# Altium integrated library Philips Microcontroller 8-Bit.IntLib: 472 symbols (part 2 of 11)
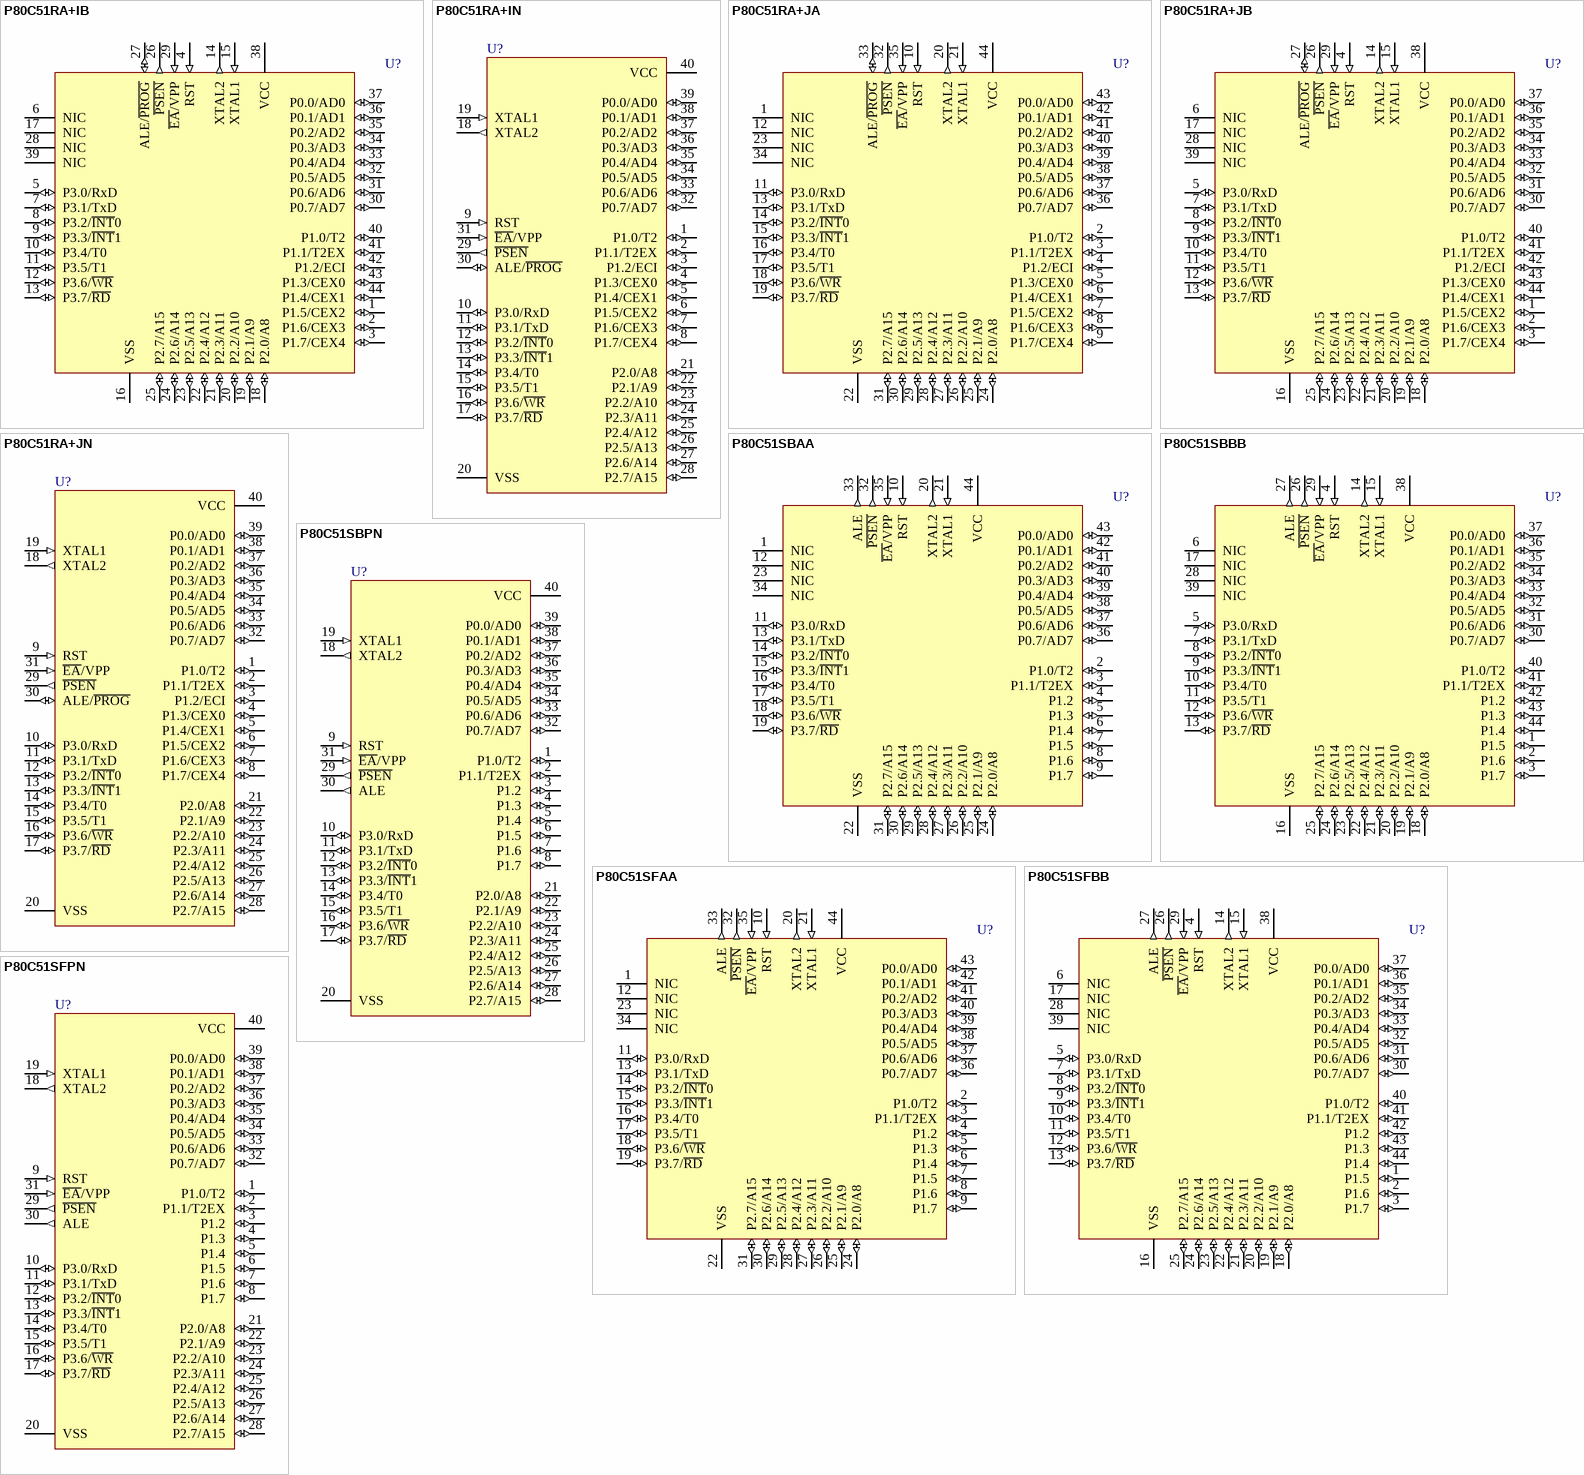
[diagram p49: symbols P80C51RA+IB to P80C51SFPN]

## P80C51RA+JB
designator U?
80C51 8-Bit Microcontroller Family: 512 B RAM, ROMless, 5V, Low Power, High Speed
footprint SOT307-2_N (QFP, 44-Leads, Body 10x10mm, Pitch 0.8mm, IPC Medium Density)
footprint SOT307-2_L (QFP, 44-Leads, Body 10x10mm, Pitch 0.8mm, IPC High Density)
footprint SOT307-2_M (QFP, 44-Leads, Body 10x10mm, Pitch 0.8mm, IPC Low Density)
pins: 1 P1.5/CEX2 (io), 2 P1.6/CEX3 (io), 3 P1.7/CEX4 (io), 4 RST (in), 5 P3.0/RxD (io), 6 NIC, 7 P3.1/TxD (io), 8 P3.2/~{INT}0 (io), 9 P3.3/~{INT}1 (io), 10 P3.4/T0 (io), 11 P3.5/T1 (io), 12 P3.6/~{WR} (io), 13 P3.7/~{RD} (io), 14 XTAL2 (out), 15 XTAL1 (in), 16 VSS (power), 17 NIC, 18 P2.0/A8 (io), 19 P2.1/A9 (io), 20 P2.2/A10 (io), 21 P2.3/A11 (io), 22 P2.4/A12 (io), 23 P2.5/A13 (io), 24 P2.6/A14 (io), 25 P2.7/A15 (io), 26 ~{PSEN} (out), 27 ALE/~{PROG} (io), 28 NIC, 29 ~{EA}/VPP (in), 30 P0.7/AD7 (io), 31 P0.6/AD6 (io), 32 P0.5/AD5 (io), 33 P0.4/AD4 (io), 34 P0.3/AD3 (io), 35 P0.2/AD2 (io), 36 P0.1/AD1 (io), 37 P0.0/AD0 (io), 38 VCC (power), 39 NIC, 40 P1.0/T2 (io), 41 P1.1/T2EX (io), 42 P1.2/ECI (io), 43 P1.3/CEX0 (io), 44 P1.4/CEX1 (io)

## P80C51RA+JN
designator U?
80C51 8-Bit Microcontroller Family: 512 B RAM, ROMless, 5V, Low Power, High Speed
footprint SOT129-1 (DIP, Plastic; 40 Leads; Row Spacing 15.24 mm; Pitch 2.54 mm)
pins: 1 P1.0/T2 (io), 2 P1.1/T2EX (io), 3 P1.2/ECI (io), 4 P1.3/CEX0 (io), 5 P1.4/CEX1 (io), 6 P1.5/CEX2 (io), 7 P1.6/CEX3 (io), 8 P1.7/CEX4 (io), 9 RST (in), 10 P3.0/RxD (io), 11 P3.1/TxD (io), 12 P3.2/~{INT}0 (io), 13 P3.3/~{INT}1 (io), 14 P3.4/T0 (io), 15 P3.5/T1 (io), 16 P3.6/~{WR} (io), 17 P3.7/~{RD} (io), 18 XTAL2 (out), 19 XTAL1 (in), 20 VSS (power), 21 P2.0/A8 (io), 22 P2.1/A9 (io), 23 P2.2/A10 (io), 24 P2.3/A11 (io), 25 P2.4/A12 (io), 26 P2.5/A13 (io), 27 P2.6/A14 (io), 28 P2.7/A15 (io), 29 ~{PSEN} (out), 30 ALE/~{PROG} (io), 31 ~{EA}/VPP (in), 32 P0.7/AD7 (io), 33 P0.6/AD6 (io), 34 P0.5/AD5 (io), 35 P0.4/AD4 (io), 36 P0.3/AD3 (io), 37 P0.2/AD2 (io), 38 P0.1/AD1 (io), 39 P0.0/AD0 (io), 40 VCC (power)

## P80C51SBAA
designator U?
80C51 8-Bit Microcontroller Family: 128 B RAM, 4 kB ROM, 2.7V-5.5V, Low Power, High Speed
footprint SOT187-2_N (Leaded Chip Carrier, 44-Leads, Body 16.6x16.6mm, Pitch 1.27mm, IPC Medium Density)
footprint SOT187-2_L (Leaded Chip Carrier, 44-Leads, Body 16.6x16.6mm, Pitch 1.27mm, IPC High Density)
footprint SOT187-2_M (Leaded Chip Carrier, 44-Leads, Body 16.6x16.6mm, Pitch 1.27mm, IPC Low Density)
pins: 1 NIC, 2 P1.0/T2 (io), 3 P1.1/T2EX (io), 4 P1.2 (io), 5 P1.3 (io), 6 P1.4 (io), 7 P1.5 (io), 8 P1.6 (io), 9 P1.7 (io), 10 RST (in), 11 P3.0/RxD (io), 12 NIC, 13 P3.1/TxD (io), 14 P3.2/~{INT}0 (io), 15 P3.3/~{INT}1 (io), 16 P3.4/T0 (io), 17 P3.5/T1 (io), 18 P3.6/~{WR} (io), 19 P3.7/~{RD} (io), 20 XTAL2 (out), 21 XTAL1 (in), 22 VSS (power), 23 NIC, 24 P2.0/A8 (io), 25 P2.1/A9 (io), 26 P2.2/A10 (io), 27 P2.3/A11 (io), 28 P2.4/A12 (io), 29 P2.5/A13 (io), 30 P2.6/A14 (io), 31 P2.7/A15 (io), 32 ~{PSEN} (out), 33 ALE (out), 34 NIC, 35 ~{EA}/VPP (in), 36 P0.7/AD7 (io), 37 P0.6/AD6 (io), 38 P0.5/AD5 (io), 39 P0.4/AD4 (io), 40 P0.3/AD3 (io), 41 P0.2/AD2 (io), 42 P0.1/AD1 (io), 43 P0.0/AD0 (io), 44 VCC (power)

## P80C51SBBB
designator U?
80C51 8-Bit Microcontroller Family: 128 B RAM, 4 kB ROM, 2.7V-5.5V, Low Power, High Speed
footprint SOT307-2_N (QFP, 44-Leads, Body 10x10mm, Pitch 0.8mm, IPC Medium Density)
footprint SOT307-2_L (QFP, 44-Leads, Body 10x10mm, Pitch 0.8mm, IPC High Density)
footprint SOT307-2_M (QFP, 44-Leads, Body 10x10mm, Pitch 0.8mm, IPC Low Density)
pins: 1 P1.5 (io), 2 P1.6 (io), 3 P1.7 (io), 4 RST (in), 5 P3.0/RxD (io), 6 NIC, 7 P3.1/TxD (io), 8 P3.2/~{INT}0 (io), 9 P3.3/~{INT}1 (io), 10 P3.4/T0 (io), 11 P3.5/T1 (io), 12 P3.6/~{WR} (io), 13 P3.7/~{RD} (io), 14 XTAL2 (out), 15 XTAL1 (in), 16 VSS (power), 17 NIC, 18 P2.0/A8 (io), 19 P2.1/A9 (io), 20 P2.2/A10 (io), 21 P2.3/A11 (io), 22 P2.4/A12 (io), 23 P2.5/A13 (io), 24 P2.6/A14 (io), 25 P2.7/A15 (io), 26 ~{PSEN} (out), 27 ALE (out), 28 NIC, 29 ~{EA}/VPP (in), 30 P0.7/AD7 (io), 31 P0.6/AD6 (io), 32 P0.5/AD5 (io), 33 P0.4/AD4 (io), 34 P0.3/AD3 (io), 35 P0.2/AD2 (io), 36 P0.1/AD1 (io), 37 P0.0/AD0 (io), 38 VCC (power), 39 NIC, 40 P1.0/T2 (io), 41 P1.1/T2EX (io), 42 P1.2 (io), 43 P1.3 (io), 44 P1.4 (io)

## P80C51SBPN
designator U?
80C51 8-Bit Microcontroller Family: 128 B RAM, 4 kB ROM, 2.7V-5.5V, Low Power, High Speed
footprint SOT129-1 (DIP, Plastic; 40 Leads; Row Spacing 15.24 mm; Pitch 2.54 mm)
pins: 1 P1.0/T2 (io), 2 P1.1/T2EX (io), 3 P1.2 (io), 4 P1.3 (io), 5 P1.4 (io), 6 P1.5 (io), 7 P1.6 (io), 8 P1.7 (io), 9 RST (in), 10 P3.0/RxD (io), 11 P3.1/TxD (io), 12 P3.2/~{INT}0 (io), 13 P3.3/~{INT}1 (io), 14 P3.4/T0 (io), 15 P3.5/T1 (io), 16 P3.6/~{WR} (io), 17 P3.7/~{RD} (io), 18 XTAL2 (out), 19 XTAL1 (in), 20 VSS (power), 21 P2.0/A8 (io), 22 P2.1/A9 (io), 23 P2.2/A10 (io), 24 P2.3/A11 (io), 25 P2.4/A12 (io), 26 P2.5/A13 (io), 27 P2.6/A14 (io), 28 P2.7/A15 (io), 29 ~{PSEN} (out), 30 ALE (out), 31 ~{EA}/VPP (in), 32 P0.7/AD7 (io), 33 P0.6/AD6 (io), 34 P0.5/AD5 (io), 35 P0.4/AD4 (io), 36 P0.3/AD3 (io), 37 P0.2/AD2 (io), 38 P0.1/AD1 (io), 39 P0.0/AD0 (io), 40 VCC (power)

## P80C51SFAA
designator U?
80C51 8-Bit Microcontroller Family: 128 B RAM, 4 kB ROM, 2.7V-5.5V, Low Power, High Speed
footprint SOT187-2_N (Leaded Chip Carrier, 44-Leads, Body 16.6x16.6mm, Pitch 1.27mm, IPC Medium Density)
footprint SOT187-2_L (Leaded Chip Carrier, 44-Leads, Body 16.6x16.6mm, Pitch 1.27mm, IPC High Density)
footprint SOT187-2_M (Leaded Chip Carrier, 44-Leads, Body 16.6x16.6mm, Pitch 1.27mm, IPC Low Density)
pins: 1 NIC, 2 P1.0/T2 (io), 3 P1.1/T2EX (io), 4 P1.2 (io), 5 P1.3 (io), 6 P1.4 (io), 7 P1.5 (io), 8 P1.6 (io), 9 P1.7 (io), 10 RST (in), 11 P3.0/RxD (io), 12 NIC, 13 P3.1/TxD (io), 14 P3.2/~{INT}0 (io), 15 P3.3/~{INT}1 (io), 16 P3.4/T0 (io), 17 P3.5/T1 (io), 18 P3.6/~{WR} (io), 19 P3.7/~{RD} (io), 20 XTAL2 (out), 21 XTAL1 (in), 22 VSS (power), 23 NIC, 24 P2.0/A8 (io), 25 P2.1/A9 (io), 26 P2.2/A10 (io), 27 P2.3/A11 (io), 28 P2.4/A12 (io), 29 P2.5/A13 (io), 30 P2.6/A14 (io), 31 P2.7/A15 (io), 32 ~{PSEN} (out), 33 ALE (out), 34 NIC, 35 ~{EA}/VPP (in), 36 P0.7/AD7 (io), 37 P0.6/AD6 (io), 38 P0.5/AD5 (io), 39 P0.4/AD4 (io), 40 P0.3/AD3 (io), 41 P0.2/AD2 (io), 42 P0.1/AD1 (io), 43 P0.0/AD0 (io), 44 VCC (power)

## P80C51SFBB
designator U?
80C51 8-Bit Microcontroller Family: 128 B RAM, 4 kB ROM, 2.7V-5.5V, Low Power, High Speed
footprint SOT307-2_N (QFP, 44-Leads, Body 10x10mm, Pitch 0.8mm, IPC Medium Density)
footprint SOT307-2_L (QFP, 44-Leads, Body 10x10mm, Pitch 0.8mm, IPC High Density)
footprint SOT307-2_M (QFP, 44-Leads, Body 10x10mm, Pitch 0.8mm, IPC Low Density)
pins: 1 P1.5 (io), 2 P1.6 (io), 3 P1.7 (io), 4 RST (in), 5 P3.0/RxD (io), 6 NIC, 7 P3.1/TxD (io), 8 P3.2/~{INT}0 (io), 9 P3.3/~{INT}1 (io), 10 P3.4/T0 (io), 11 P3.5/T1 (io), 12 P3.6/~{WR} (io), 13 P3.7/~{RD} (io), 14 XTAL2 (out), 15 XTAL1 (in), 16 VSS (power), 17 NIC, 18 P2.0/A8 (io), 19 P2.1/A9 (io), 20 P2.2/A10 (io), 21 P2.3/A11 (io), 22 P2.4/A12 (io), 23 P2.5/A13 (io), 24 P2.6/A14 (io), 25 P2.7/A15 (io), 26 ~{PSEN} (out), 27 ALE (out), 28 NIC, 29 ~{EA}/VPP (in), 30 P0.7/AD7 (io), 31 P0.6/AD6 (io), 32 P0.5/AD5 (io), 33 P0.4/AD4 (io), 34 P0.3/AD3 (io), 35 P0.2/AD2 (io), 36 P0.1/AD1 (io), 37 P0.0/AD0 (io), 38 VCC (power), 39 NIC, 40 P1.0/T2 (io), 41 P1.1/T2EX (io), 42 P1.2 (io), 43 P1.3 (io), 44 P1.4 (io)

## P80C51SFPN
designator U?
80C51 8-Bit Microcontroller Family: 128 B RAM, 4 kB ROM, 2.7V-5.5V, Low Power, High Speed
footprint SOT129-1 (DIP, Plastic; 40 Leads; Row Spacing 15.24 mm; Pitch 2.54 mm)
pins: 1 P1.0/T2 (io), 2 P1.1/T2EX (io), 3 P1.2 (io), 4 P1.3 (io), 5 P1.4 (io), 6 P1.5 (io), 7 P1.6 (io), 8 P1.7 (io), 9 RST (in), 10 P3.0/RxD (io), 11 P3.1/TxD (io), 12 P3.2/~{INT}0 (io), 13 P3.3/~{INT}1 (io), 14 P3.4/T0 (io), 15 P3.5/T1 (io), 16 P3.6/~{WR} (io), 17 P3.7/~{RD} (io), 18 XTAL2 (out), 19 XTAL1 (in), 20 VSS (power), 21 P2.0/A8 (io), 22 P2.1/A9 (io), 23 P2.2/A10 (io), 24 P2.3/A11 (io), 25 P2.4/A12 (io), 26 P2.5/A13 (io), 27 P2.6/A14 (io), 28 P2.7/A15 (io), 29 ~{PSEN} (out), 30 ALE (out), 31 ~{EA}/VPP (in), 32 P0.7/AD7 (io), 33 P0.6/AD6 (io), 34 P0.5/AD5 (io), 35 P0.4/AD4 (io), 36 P0.3/AD3 (io), 37 P0.2/AD2 (io), 38 P0.1/AD1 (io), 39 P0.0/AD0 (io), 40 VCC (power)

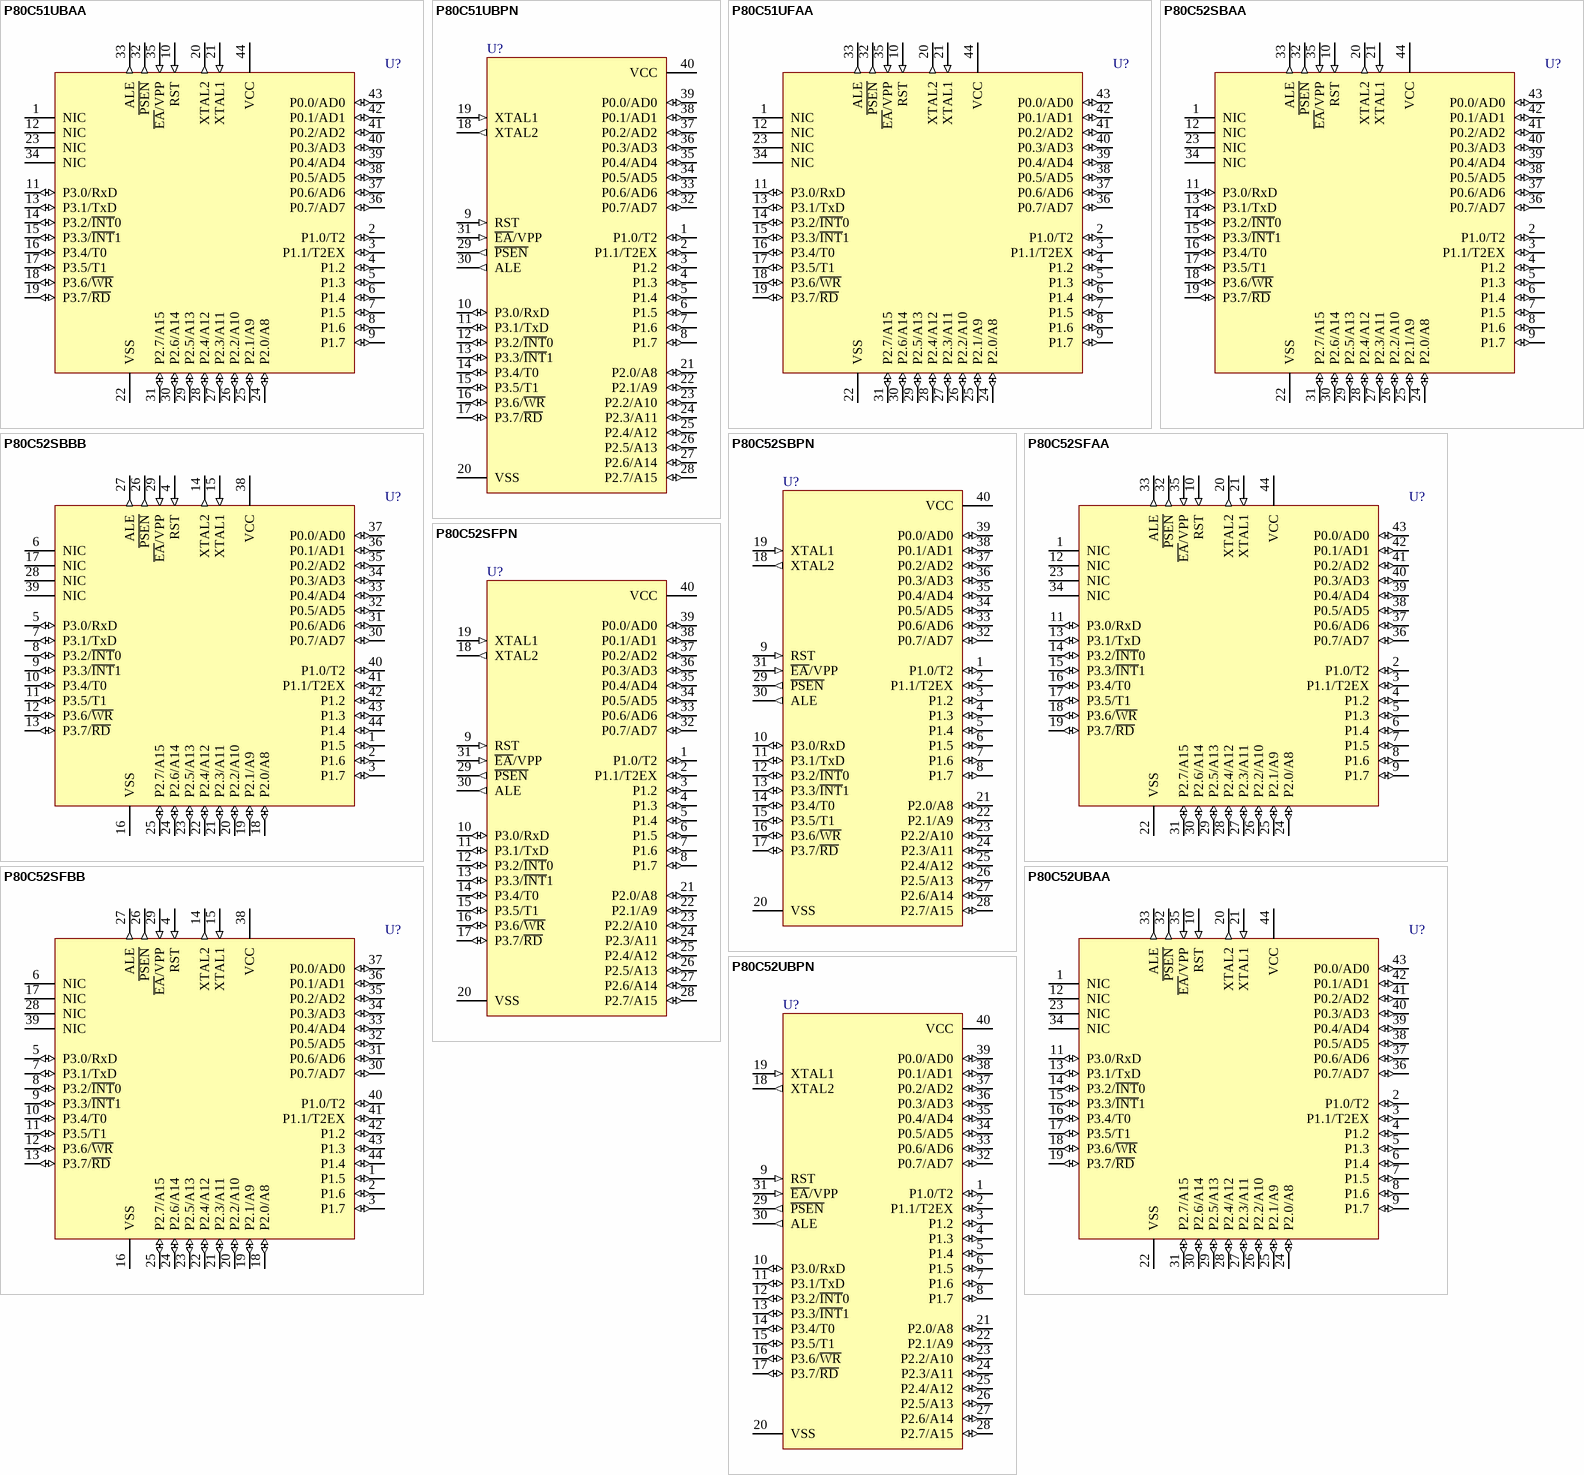
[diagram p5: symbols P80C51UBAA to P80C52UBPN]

## P80C51UBAA
designator U?
80C51 8-Bit Microcontroller Family: 128 B RAM, 4 kB ROM, 5V, Low Power, High Speed
footprint SOT187-2_N (Leaded Chip Carrier, 44-Leads, Body 16.6x16.6mm, Pitch 1.27mm, IPC Medium Density)
footprint SOT187-2_L (Leaded Chip Carrier, 44-Leads, Body 16.6x16.6mm, Pitch 1.27mm, IPC High Density)
footprint SOT187-2_M (Leaded Chip Carrier, 44-Leads, Body 16.6x16.6mm, Pitch 1.27mm, IPC Low Density)
pins: 1 NIC, 2 P1.0/T2 (io), 3 P1.1/T2EX (io), 4 P1.2 (io), 5 P1.3 (io), 6 P1.4 (io), 7 P1.5 (io), 8 P1.6 (io), 9 P1.7 (io), 10 RST (in), 11 P3.0/RxD (io), 12 NIC, 13 P3.1/TxD (io), 14 P3.2/~{INT}0 (io), 15 P3.3/~{INT}1 (io), 16 P3.4/T0 (io), 17 P3.5/T1 (io), 18 P3.6/~{WR} (io), 19 P3.7/~{RD} (io), 20 XTAL2 (out), 21 XTAL1 (in), 22 VSS (power), 23 NIC, 24 P2.0/A8 (io), 25 P2.1/A9 (io), 26 P2.2/A10 (io), 27 P2.3/A11 (io), 28 P2.4/A12 (io), 29 P2.5/A13 (io), 30 P2.6/A14 (io), 31 P2.7/A15 (io), 32 ~{PSEN} (out), 33 ALE (out), 34 NIC, 35 ~{EA}/VPP (in), 36 P0.7/AD7 (io), 37 P0.6/AD6 (io), 38 P0.5/AD5 (io), 39 P0.4/AD4 (io), 40 P0.3/AD3 (io), 41 P0.2/AD2 (io), 42 P0.1/AD1 (io), 43 P0.0/AD0 (io), 44 VCC (power)

## P80C51UBPN
designator U?
80C51 8-Bit Microcontroller Family: 128 B RAM, 4 kB ROM, 5V, Low Power, High Speed
footprint SOT129-1 (DIP, Plastic; 40 Leads; Row Spacing 15.24 mm; Pitch 2.54 mm)
pins: 1 P1.0/T2 (io), 2 P1.1/T2EX (io), 3 P1.2 (io), 4 P1.3 (io), 5 P1.4 (io), 6 P1.5 (io), 7 P1.6 (io), 8 P1.7 (io), 9 RST (in), 10 P3.0/RxD (io), 11 P3.1/TxD (io), 12 P3.2/~{INT}0 (io), 13 P3.3/~{INT}1 (io), 14 P3.4/T0 (io), 15 P3.5/T1 (io), 16 P3.6/~{WR} (io), 17 P3.7/~{RD} (io), 18 XTAL2 (out), 19 XTAL1 (in), 20 VSS (power), 21 P2.0/A8 (io), 22 P2.1/A9 (io), 23 P2.2/A10 (io), 24 P2.3/A11 (io), 25 P2.4/A12 (io), 26 P2.5/A13 (io), 27 P2.6/A14 (io), 28 P2.7/A15 (io), 29 ~{PSEN} (out), 30 ALE (out), 31 ~{EA}/VPP (in), 32 P0.7/AD7 (io), 33 P0.6/AD6 (io), 34 P0.5/AD5 (io), 35 P0.4/AD4 (io), 36 P0.3/AD3 (io), 37 P0.2/AD2 (io), 38 P0.1/AD1 (io), 39 P0.0/AD0 (io), 40 VCC (power)

## P80C51UFAA
designator U?
80C51 8-Bit Microcontroller Family: 128 B RAM, 4 kB ROM, 5V, Low Power, High Speed
footprint SOT187-2_N (Leaded Chip Carrier, 44-Leads, Body 16.6x16.6mm, Pitch 1.27mm, IPC Medium Density)
footprint SOT187-2_L (Leaded Chip Carrier, 44-Leads, Body 16.6x16.6mm, Pitch 1.27mm, IPC High Density)
footprint SOT187-2_M (Leaded Chip Carrier, 44-Leads, Body 16.6x16.6mm, Pitch 1.27mm, IPC Low Density)
pins: 1 NIC, 2 P1.0/T2 (io), 3 P1.1/T2EX (io), 4 P1.2 (io), 5 P1.3 (io), 6 P1.4 (io), 7 P1.5 (io), 8 P1.6 (io), 9 P1.7 (io), 10 RST (in), 11 P3.0/RxD (io), 12 NIC, 13 P3.1/TxD (io), 14 P3.2/~{INT}0 (io), 15 P3.3/~{INT}1 (io), 16 P3.4/T0 (io), 17 P3.5/T1 (io), 18 P3.6/~{WR} (io), 19 P3.7/~{RD} (io), 20 XTAL2 (out), 21 XTAL1 (in), 22 VSS (power), 23 NIC, 24 P2.0/A8 (io), 25 P2.1/A9 (io), 26 P2.2/A10 (io), 27 P2.3/A11 (io), 28 P2.4/A12 (io), 29 P2.5/A13 (io), 30 P2.6/A14 (io), 31 P2.7/A15 (io), 32 ~{PSEN} (out), 33 ALE (out), 34 NIC, 35 ~{EA}/VPP (in), 36 P0.7/AD7 (io), 37 P0.6/AD6 (io), 38 P0.5/AD5 (io), 39 P0.4/AD4 (io), 40 P0.3/AD3 (io), 41 P0.2/AD2 (io), 42 P0.1/AD1 (io), 43 P0.0/AD0 (io), 44 VCC (power)

## P80C52SBAA
designator U?
80C51 8-Bit Microcontroller Family: 256 B RAM, 8 kB ROM, 2.7V-5.5V, Low Power, High Speed
footprint SOT187-2_N (Leaded Chip Carrier, 44-Leads, Body 16.6x16.6mm, Pitch 1.27mm, IPC Medium Density)
footprint SOT187-2_L (Leaded Chip Carrier, 44-Leads, Body 16.6x16.6mm, Pitch 1.27mm, IPC High Density)
footprint SOT187-2_M (Leaded Chip Carrier, 44-Leads, Body 16.6x16.6mm, Pitch 1.27mm, IPC Low Density)
pins: 1 NIC, 2 P1.0/T2 (io), 3 P1.1/T2EX (io), 4 P1.2 (io), 5 P1.3 (io), 6 P1.4 (io), 7 P1.5 (io), 8 P1.6 (io), 9 P1.7 (io), 10 RST (in), 11 P3.0/RxD (io), 12 NIC, 13 P3.1/TxD (io), 14 P3.2/~{INT}0 (io), 15 P3.3/~{INT}1 (io), 16 P3.4/T0 (io), 17 P3.5/T1 (io), 18 P3.6/~{WR} (io), 19 P3.7/~{RD} (io), 20 XTAL2 (out), 21 XTAL1 (in), 22 VSS (power), 23 NIC, 24 P2.0/A8 (io), 25 P2.1/A9 (io), 26 P2.2/A10 (io), 27 P2.3/A11 (io), 28 P2.4/A12 (io), 29 P2.5/A13 (io), 30 P2.6/A14 (io), 31 P2.7/A15 (io), 32 ~{PSEN} (out), 33 ALE (out), 34 NIC, 35 ~{EA}/VPP (in), 36 P0.7/AD7 (io), 37 P0.6/AD6 (io), 38 P0.5/AD5 (io), 39 P0.4/AD4 (io), 40 P0.3/AD3 (io), 41 P0.2/AD2 (io), 42 P0.1/AD1 (io), 43 P0.0/AD0 (io), 44 VCC (power)

## P80C52SBBB
designator U?
80C51 8-Bit Microcontroller Family: 256 B RAM, 8 kB ROM, 2.7V-5.5V, Low Power, High Speed
footprint SOT307-2_N (QFP, 44-Leads, Body 10x10mm, Pitch 0.8mm, IPC Medium Density)
footprint SOT307-2_L (QFP, 44-Leads, Body 10x10mm, Pitch 0.8mm, IPC High Density)
footprint SOT307-2_M (QFP, 44-Leads, Body 10x10mm, Pitch 0.8mm, IPC Low Density)
pins: 1 P1.5 (io), 2 P1.6 (io), 3 P1.7 (io), 4 RST (in), 5 P3.0/RxD (io), 6 NIC, 7 P3.1/TxD (io), 8 P3.2/~{INT}0 (io), 9 P3.3/~{INT}1 (io), 10 P3.4/T0 (io), 11 P3.5/T1 (io), 12 P3.6/~{WR} (io), 13 P3.7/~{RD} (io), 14 XTAL2 (out), 15 XTAL1 (in), 16 VSS (power), 17 NIC, 18 P2.0/A8 (io), 19 P2.1/A9 (io), 20 P2.2/A10 (io), 21 P2.3/A11 (io), 22 P2.4/A12 (io), 23 P2.5/A13 (io), 24 P2.6/A14 (io), 25 P2.7/A15 (io), 26 ~{PSEN} (out), 27 ALE (out), 28 NIC, 29 ~{EA}/VPP (in), 30 P0.7/AD7 (io), 31 P0.6/AD6 (io), 32 P0.5/AD5 (io), 33 P0.4/AD4 (io), 34 P0.3/AD3 (io), 35 P0.2/AD2 (io), 36 P0.1/AD1 (io), 37 P0.0/AD0 (io), 38 VCC (power), 39 NIC, 40 P1.0/T2 (io), 41 P1.1/T2EX (io), 42 P1.2 (io), 43 P1.3 (io), 44 P1.4 (io)

## P80C52SBPN
designator U?
80C51 8-Bit Microcontroller Family: 256 B RAM, 8 kB ROM, 2.7V-5.5V, Low Power, High Speed
footprint SOT129-1 (DIP, Plastic; 40 Leads; Row Spacing 15.24 mm; Pitch 2.54 mm)
pins: 1 P1.0/T2 (io), 2 P1.1/T2EX (io), 3 P1.2 (io), 4 P1.3 (io), 5 P1.4 (io), 6 P1.5 (io), 7 P1.6 (io), 8 P1.7 (io), 9 RST (in), 10 P3.0/RxD (io), 11 P3.1/TxD (io), 12 P3.2/~{INT}0 (io), 13 P3.3/~{INT}1 (io), 14 P3.4/T0 (io), 15 P3.5/T1 (io), 16 P3.6/~{WR} (io), 17 P3.7/~{RD} (io), 18 XTAL2 (out), 19 XTAL1 (in), 20 VSS (power), 21 P2.0/A8 (io), 22 P2.1/A9 (io), 23 P2.2/A10 (io), 24 P2.3/A11 (io), 25 P2.4/A12 (io), 26 P2.5/A13 (io), 27 P2.6/A14 (io), 28 P2.7/A15 (io), 29 ~{PSEN} (out), 30 ALE (out), 31 ~{EA}/VPP (in), 32 P0.7/AD7 (io), 33 P0.6/AD6 (io), 34 P0.5/AD5 (io), 35 P0.4/AD4 (io), 36 P0.3/AD3 (io), 37 P0.2/AD2 (io), 38 P0.1/AD1 (io), 39 P0.0/AD0 (io), 40 VCC (power)

## P80C52SFAA
designator U?
80C51 8-Bit Microcontroller Family: 256 B RAM, 8 kB ROM, 2.7V-5.5V, Low Power, High Speed
footprint SOT187-2_N (Leaded Chip Carrier, 44-Leads, Body 16.6x16.6mm, Pitch 1.27mm, IPC Medium Density)
footprint SOT187-2_L (Leaded Chip Carrier, 44-Leads, Body 16.6x16.6mm, Pitch 1.27mm, IPC High Density)
footprint SOT187-2_M (Leaded Chip Carrier, 44-Leads, Body 16.6x16.6mm, Pitch 1.27mm, IPC Low Density)
pins: 1 NIC, 2 P1.0/T2 (io), 3 P1.1/T2EX (io), 4 P1.2 (io), 5 P1.3 (io), 6 P1.4 (io), 7 P1.5 (io), 8 P1.6 (io), 9 P1.7 (io), 10 RST (in), 11 P3.0/RxD (io), 12 NIC, 13 P3.1/TxD (io), 14 P3.2/~{INT}0 (io), 15 P3.3/~{INT}1 (io), 16 P3.4/T0 (io), 17 P3.5/T1 (io), 18 P3.6/~{WR} (io), 19 P3.7/~{RD} (io), 20 XTAL2 (out), 21 XTAL1 (in), 22 VSS (power), 23 NIC, 24 P2.0/A8 (io), 25 P2.1/A9 (io), 26 P2.2/A10 (io), 27 P2.3/A11 (io), 28 P2.4/A12 (io), 29 P2.5/A13 (io), 30 P2.6/A14 (io), 31 P2.7/A15 (io), 32 ~{PSEN} (out), 33 ALE (out), 34 NIC, 35 ~{EA}/VPP (in), 36 P0.7/AD7 (io), 37 P0.6/AD6 (io), 38 P0.5/AD5 (io), 39 P0.4/AD4 (io), 40 P0.3/AD3 (io), 41 P0.2/AD2 (io), 42 P0.1/AD1 (io), 43 P0.0/AD0 (io), 44 VCC (power)

## P80C52SFBB
designator U?
80C51 8-Bit Microcontroller Family: 256 B RAM, 8 kB ROM, 2.7V-5.5V, Low Power, High Speed
footprint SOT307-2_N (QFP, 44-Leads, Body 10x10mm, Pitch 0.8mm, IPC Medium Density)
footprint SOT307-2_L (QFP, 44-Leads, Body 10x10mm, Pitch 0.8mm, IPC High Density)
footprint SOT307-2_M (QFP, 44-Leads, Body 10x10mm, Pitch 0.8mm, IPC Low Density)
pins: 1 P1.5 (io), 2 P1.6 (io), 3 P1.7 (io), 4 RST (in), 5 P3.0/RxD (io), 6 NIC, 7 P3.1/TxD (io), 8 P3.2/~{INT}0 (io), 9 P3.3/~{INT}1 (io), 10 P3.4/T0 (io), 11 P3.5/T1 (io), 12 P3.6/~{WR} (io), 13 P3.7/~{RD} (io), 14 XTAL2 (out), 15 XTAL1 (in), 16 VSS (power), 17 NIC, 18 P2.0/A8 (io), 19 P2.1/A9 (io), 20 P2.2/A10 (io), 21 P2.3/A11 (io), 22 P2.4/A12 (io), 23 P2.5/A13 (io), 24 P2.6/A14 (io), 25 P2.7/A15 (io), 26 ~{PSEN} (out), 27 ALE (out), 28 NIC, 29 ~{EA}/VPP (in), 30 P0.7/AD7 (io), 31 P0.6/AD6 (io), 32 P0.5/AD5 (io), 33 P0.4/AD4 (io), 34 P0.3/AD3 (io), 35 P0.2/AD2 (io), 36 P0.1/AD1 (io), 37 P0.0/AD0 (io), 38 VCC (power), 39 NIC, 40 P1.0/T2 (io), 41 P1.1/T2EX (io), 42 P1.2 (io), 43 P1.3 (io), 44 P1.4 (io)

## P80C52SFPN
designator U?
80C51 8-Bit Microcontroller Family: 256 B RAM, 8 kB ROM, 2.7V-5.5V, Low Power, High Speed
footprint SOT129-1 (DIP, Plastic; 40 Leads; Row Spacing 15.24 mm; Pitch 2.54 mm)
pins: 1 P1.0/T2 (io), 2 P1.1/T2EX (io), 3 P1.2 (io), 4 P1.3 (io), 5 P1.4 (io), 6 P1.5 (io), 7 P1.6 (io), 8 P1.7 (io), 9 RST (in), 10 P3.0/RxD (io), 11 P3.1/TxD (io), 12 P3.2/~{INT}0 (io), 13 P3.3/~{INT}1 (io), 14 P3.4/T0 (io), 15 P3.5/T1 (io), 16 P3.6/~{WR} (io), 17 P3.7/~{RD} (io), 18 XTAL2 (out), 19 XTAL1 (in), 20 VSS (power), 21 P2.0/A8 (io), 22 P2.1/A9 (io), 23 P2.2/A10 (io), 24 P2.3/A11 (io), 25 P2.4/A12 (io), 26 P2.5/A13 (io), 27 P2.6/A14 (io), 28 P2.7/A15 (io), 29 ~{PSEN} (out), 30 ALE (out), 31 ~{EA}/VPP (in), 32 P0.7/AD7 (io), 33 P0.6/AD6 (io), 34 P0.5/AD5 (io), 35 P0.4/AD4 (io), 36 P0.3/AD3 (io), 37 P0.2/AD2 (io), 38 P0.1/AD1 (io), 39 P0.0/AD0 (io), 40 VCC (power)

## P80C52UBAA
designator U?
80C51 8-Bit Microcontroller Family: 256 B RAM, 8 kB ROM, 5V, Low Power, High Speed
footprint SOT187-2_N (Leaded Chip Carrier, 44-Leads, Body 16.6x16.6mm, Pitch 1.27mm, IPC Medium Density)
footprint SOT187-2_L (Leaded Chip Carrier, 44-Leads, Body 16.6x16.6mm, Pitch 1.27mm, IPC High Density)
footprint SOT187-2_M (Leaded Chip Carrier, 44-Leads, Body 16.6x16.6mm, Pitch 1.27mm, IPC Low Density)
pins: 1 NIC, 2 P1.0/T2 (io), 3 P1.1/T2EX (io), 4 P1.2 (io), 5 P1.3 (io), 6 P1.4 (io), 7 P1.5 (io), 8 P1.6 (io), 9 P1.7 (io), 10 RST (in), 11 P3.0/RxD (io), 12 NIC, 13 P3.1/TxD (io), 14 P3.2/~{INT}0 (io), 15 P3.3/~{INT}1 (io), 16 P3.4/T0 (io), 17 P3.5/T1 (io), 18 P3.6/~{WR} (io), 19 P3.7/~{RD} (io), 20 XTAL2 (out), 21 XTAL1 (in), 22 VSS (power), 23 NIC, 24 P2.0/A8 (io), 25 P2.1/A9 (io), 26 P2.2/A10 (io), 27 P2.3/A11 (io), 28 P2.4/A12 (io), 29 P2.5/A13 (io), 30 P2.6/A14 (io), 31 P2.7/A15 (io), 32 ~{PSEN} (out), 33 ALE (out), 34 NIC, 35 ~{EA}/VPP (in), 36 P0.7/AD7 (io), 37 P0.6/AD6 (io), 38 P0.5/AD5 (io), 39 P0.4/AD4 (io), 40 P0.3/AD3 (io), 41 P0.2/AD2 (io), 42 P0.1/AD1 (io), 43 P0.0/AD0 (io), 44 VCC (power)

## P80C52UBPN
designator U?
80C51 8-Bit Microcontroller Family: 256 B RAM, 8 kB ROM, 5V, Low Power, High Speed
footprint SOT129-1 (DIP, Plastic; 40 Leads; Row Spacing 15.24 mm; Pitch 2.54 mm)
pins: 1 P1.0/T2 (io), 2 P1.1/T2EX (io), 3 P1.2 (io), 4 P1.3 (io), 5 P1.4 (io), 6 P1.5 (io), 7 P1.6 (io), 8 P1.7 (io), 9 RST (in), 10 P3.0/RxD (io), 11 P3.1/TxD (io), 12 P3.2/~{INT}0 (io), 13 P3.3/~{INT}1 (io), 14 P3.4/T0 (io), 15 P3.5/T1 (io), 16 P3.6/~{WR} (io), 17 P3.7/~{RD} (io), 18 XTAL2 (out), 19 XTAL1 (in), 20 VSS (power), 21 P2.0/A8 (io), 22 P2.1/A9 (io), 23 P2.2/A10 (io), 24 P2.3/A11 (io), 25 P2.4/A12 (io), 26 P2.5/A13 (io), 27 P2.6/A14 (io), 28 P2.7/A15 (io), 29 ~{PSEN} (out), 30 ALE (out), 31 ~{EA}/VPP (in), 32 P0.7/AD7 (io), 33 P0.6/AD6 (io), 34 P0.5/AD5 (io), 35 P0.4/AD4 (io), 36 P0.3/AD3 (io), 37 P0.2/AD2 (io), 38 P0.1/AD1 (io), 39 P0.0/AD0 (io), 40 VCC (power)

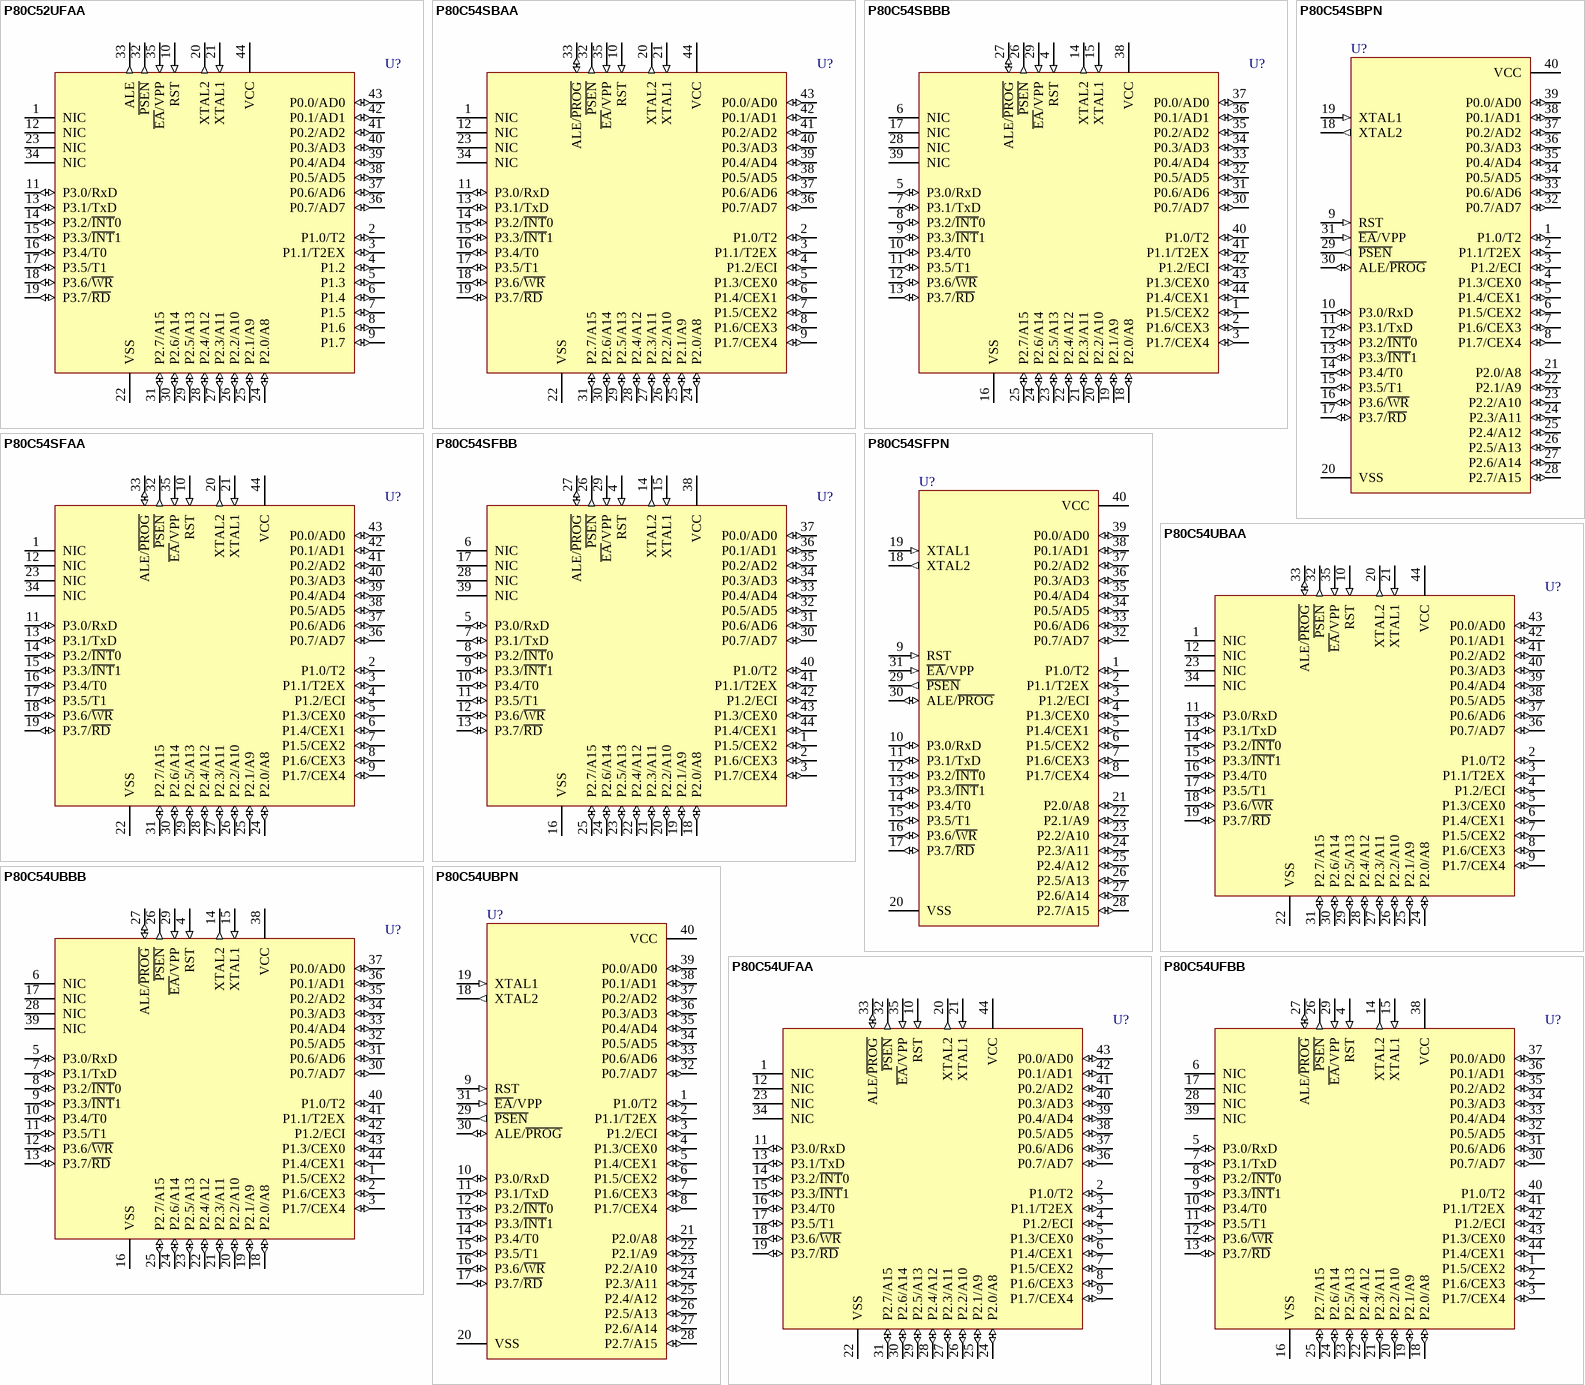
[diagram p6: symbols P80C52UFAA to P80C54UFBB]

## P80C52UFAA
designator U?
80C51 8-Bit Microcontroller Family: 256 B RAM, 8 kB ROM, 5V, Low Power, High Speed
footprint SOT187-2_N (Leaded Chip Carrier, 44-Leads, Body 16.6x16.6mm, Pitch 1.27mm, IPC Medium Density)
footprint SOT187-2_L (Leaded Chip Carrier, 44-Leads, Body 16.6x16.6mm, Pitch 1.27mm, IPC High Density)
footprint SOT187-2_M (Leaded Chip Carrier, 44-Leads, Body 16.6x16.6mm, Pitch 1.27mm, IPC Low Density)
pins: 1 NIC, 2 P1.0/T2 (io), 3 P1.1/T2EX (io), 4 P1.2 (io), 5 P1.3 (io), 6 P1.4 (io), 7 P1.5 (io), 8 P1.6 (io), 9 P1.7 (io), 10 RST (in), 11 P3.0/RxD (io), 12 NIC, 13 P3.1/TxD (io), 14 P3.2/~{INT}0 (io), 15 P3.3/~{INT}1 (io), 16 P3.4/T0 (io), 17 P3.5/T1 (io), 18 P3.6/~{WR} (io), 19 P3.7/~{RD} (io), 20 XTAL2 (out), 21 XTAL1 (in), 22 VSS (power), 23 NIC, 24 P2.0/A8 (io), 25 P2.1/A9 (io), 26 P2.2/A10 (io), 27 P2.3/A11 (io), 28 P2.4/A12 (io), 29 P2.5/A13 (io), 30 P2.6/A14 (io), 31 P2.7/A15 (io), 32 ~{PSEN} (out), 33 ALE (out), 34 NIC, 35 ~{EA}/VPP (in), 36 P0.7/AD7 (io), 37 P0.6/AD6 (io), 38 P0.5/AD5 (io), 39 P0.4/AD4 (io), 40 P0.3/AD3 (io), 41 P0.2/AD2 (io), 42 P0.1/AD1 (io), 43 P0.0/AD0 (io), 44 VCC (power)

## P80C54SBAA
designator U?
80C51 8-Bit Microcontroller Family: 256 B RAM, 16 kB ROM, 2.7V-5.5V, Low Power, High Speed
footprint SOT187-2_N (Leaded Chip Carrier, 44-Leads, Body 16.6x16.6mm, Pitch 1.27mm, IPC Medium Density)
footprint SOT187-2_L (Leaded Chip Carrier, 44-Leads, Body 16.6x16.6mm, Pitch 1.27mm, IPC High Density)
footprint SOT187-2_M (Leaded Chip Carrier, 44-Leads, Body 16.6x16.6mm, Pitch 1.27mm, IPC Low Density)
pins: 1 NIC, 2 P1.0/T2 (io), 3 P1.1/T2EX (io), 4 P1.2/ECI (io), 5 P1.3/CEX0 (io), 6 P1.4/CEX1 (io), 7 P1.5/CEX2 (io), 8 P1.6/CEX3 (io), 9 P1.7/CEX4 (io), 10 RST (in), 11 P3.0/RxD (io), 12 NIC, 13 P3.1/TxD (io), 14 P3.2/~{INT}0 (io), 15 P3.3/~{INT}1 (io), 16 P3.4/T0 (io), 17 P3.5/T1 (io), 18 P3.6/~{WR} (io), 19 P3.7/~{RD} (io), 20 XTAL2 (out), 21 XTAL1 (in), 22 VSS (power), 23 NIC, 24 P2.0/A8 (io), 25 P2.1/A9 (io), 26 P2.2/A10 (io), 27 P2.3/A11 (io), 28 P2.4/A12 (io), 29 P2.5/A13 (io), 30 P2.6/A14 (io), 31 P2.7/A15 (io), 32 ~{PSEN} (out), 33 ALE/~{PROG} (io), 34 NIC, 35 ~{EA}/VPP (in), 36 P0.7/AD7 (io), 37 P0.6/AD6 (io), 38 P0.5/AD5 (io), 39 P0.4/AD4 (io), 40 P0.3/AD3 (io), 41 P0.2/AD2 (io), 42 P0.1/AD1 (io), 43 P0.0/AD0 (io), 44 VCC (power)

## P80C54SBBB
designator U?
80C51 8-Bit Microcontroller Family: 256 B RAM, 16 kB ROM, 2.7V-5.5V, Low Power, High Speed
footprint SOT307-2_N (QFP, 44-Leads, Body 10x10mm, Pitch 0.8mm, IPC Medium Density)
footprint SOT307-2_L (QFP, 44-Leads, Body 10x10mm, Pitch 0.8mm, IPC High Density)
footprint SOT307-2_M (QFP, 44-Leads, Body 10x10mm, Pitch 0.8mm, IPC Low Density)
pins: 1 P1.5/CEX2 (io), 2 P1.6/CEX3 (io), 3 P1.7/CEX4 (io), 4 RST (in), 5 P3.0/RxD (io), 6 NIC, 7 P3.1/TxD (io), 8 P3.2/~{INT}0 (io), 9 P3.3/~{INT}1 (io), 10 P3.4/T0 (io), 11 P3.5/T1 (io), 12 P3.6/~{WR} (io), 13 P3.7/~{RD} (io), 14 XTAL2 (out), 15 XTAL1 (in), 16 VSS (power), 17 NIC, 18 P2.0/A8 (io), 19 P2.1/A9 (io), 20 P2.2/A10 (io), 21 P2.3/A11 (io), 22 P2.4/A12 (io), 23 P2.5/A13 (io), 24 P2.6/A14 (io), 25 P2.7/A15 (io), 26 ~{PSEN} (out), 27 ALE/~{PROG} (io), 28 NIC, 29 ~{EA}/VPP (in), 30 P0.7/AD7 (io), 31 P0.6/AD6 (io), 32 P0.5/AD5 (io), 33 P0.4/AD4 (io), 34 P0.3/AD3 (io), 35 P0.2/AD2 (io), 36 P0.1/AD1 (io), 37 P0.0/AD0 (io), 38 VCC (power), 39 NIC, 40 P1.0/T2 (io), 41 P1.1/T2EX (io), 42 P1.2/ECI (io), 43 P1.3/CEX0 (io), 44 P1.4/CEX1 (io)

## P80C54SBPN
designator U?
80C51 8-Bit Microcontroller Family: 256 B RAM, 16 kB ROM, 2.7V-5.5V, Low Power, High Speed
footprint SOT129-1 (DIP, Plastic; 40 Leads; Row Spacing 15.24 mm; Pitch 2.54 mm)
pins: 1 P1.0/T2 (io), 2 P1.1/T2EX (io), 3 P1.2/ECI (io), 4 P1.3/CEX0 (io), 5 P1.4/CEX1 (io), 6 P1.5/CEX2 (io), 7 P1.6/CEX3 (io), 8 P1.7/CEX4 (io), 9 RST (in), 10 P3.0/RxD (io), 11 P3.1/TxD (io), 12 P3.2/~{INT}0 (io), 13 P3.3/~{INT}1 (io), 14 P3.4/T0 (io), 15 P3.5/T1 (io), 16 P3.6/~{WR} (io), 17 P3.7/~{RD} (io), 18 XTAL2 (out), 19 XTAL1 (in), 20 VSS (power), 21 P2.0/A8 (io), 22 P2.1/A9 (io), 23 P2.2/A10 (io), 24 P2.3/A11 (io), 25 P2.4/A12 (io), 26 P2.5/A13 (io), 27 P2.6/A14 (io), 28 P2.7/A15 (io), 29 ~{PSEN} (out), 30 ALE/~{PROG} (io), 31 ~{EA}/VPP (in), 32 P0.7/AD7 (io), 33 P0.6/AD6 (io), 34 P0.5/AD5 (io), 35 P0.4/AD4 (io), 36 P0.3/AD3 (io), 37 P0.2/AD2 (io), 38 P0.1/AD1 (io), 39 P0.0/AD0 (io), 40 VCC (power)

## P80C54SFAA
designator U?
80C51 8-Bit Microcontroller Family: 256 B RAM, 16 kB ROM, 2.7V-5.5V, Low Power, High Speed
footprint SOT187-2_N (Leaded Chip Carrier, 44-Leads, Body 16.6x16.6mm, Pitch 1.27mm, IPC Medium Density)
footprint SOT187-2_L (Leaded Chip Carrier, 44-Leads, Body 16.6x16.6mm, Pitch 1.27mm, IPC High Density)
footprint SOT187-2_M (Leaded Chip Carrier, 44-Leads, Body 16.6x16.6mm, Pitch 1.27mm, IPC Low Density)
pins: 1 NIC, 2 P1.0/T2 (io), 3 P1.1/T2EX (io), 4 P1.2/ECI (io), 5 P1.3/CEX0 (io), 6 P1.4/CEX1 (io), 7 P1.5/CEX2 (io), 8 P1.6/CEX3 (io), 9 P1.7/CEX4 (io), 10 RST (in), 11 P3.0/RxD (io), 12 NIC, 13 P3.1/TxD (io), 14 P3.2/~{INT}0 (io), 15 P3.3/~{INT}1 (io), 16 P3.4/T0 (io), 17 P3.5/T1 (io), 18 P3.6/~{WR} (io), 19 P3.7/~{RD} (io), 20 XTAL2 (out), 21 XTAL1 (in), 22 VSS (power), 23 NIC, 24 P2.0/A8 (io), 25 P2.1/A9 (io), 26 P2.2/A10 (io), 27 P2.3/A11 (io), 28 P2.4/A12 (io), 29 P2.5/A13 (io), 30 P2.6/A14 (io), 31 P2.7/A15 (io), 32 ~{PSEN} (out), 33 ALE/~{PROG} (io), 34 NIC, 35 ~{EA}/VPP (in), 36 P0.7/AD7 (io), 37 P0.6/AD6 (io), 38 P0.5/AD5 (io), 39 P0.4/AD4 (io), 40 P0.3/AD3 (io), 41 P0.2/AD2 (io), 42 P0.1/AD1 (io), 43 P0.0/AD0 (io), 44 VCC (power)

## P80C54SFBB
designator U?
80C51 8-Bit Microcontroller Family: 256 B RAM, 16 kB ROM, 2.7V-5.5V, Low Power, High Speed
footprint SOT307-2_N (QFP, 44-Leads, Body 10x10mm, Pitch 0.8mm, IPC Medium Density)
footprint SOT307-2_L (QFP, 44-Leads, Body 10x10mm, Pitch 0.8mm, IPC High Density)
footprint SOT307-2_M (QFP, 44-Leads, Body 10x10mm, Pitch 0.8mm, IPC Low Density)
pins: 1 P1.5/CEX2 (io), 2 P1.6/CEX3 (io), 3 P1.7/CEX4 (io), 4 RST (in), 5 P3.0/RxD (io), 6 NIC, 7 P3.1/TxD (io), 8 P3.2/~{INT}0 (io), 9 P3.3/~{INT}1 (io), 10 P3.4/T0 (io), 11 P3.5/T1 (io), 12 P3.6/~{WR} (io), 13 P3.7/~{RD} (io), 14 XTAL2 (out), 15 XTAL1 (in), 16 VSS (power), 17 NIC, 18 P2.0/A8 (io), 19 P2.1/A9 (io), 20 P2.2/A10 (io), 21 P2.3/A11 (io), 22 P2.4/A12 (io), 23 P2.5/A13 (io), 24 P2.6/A14 (io), 25 P2.7/A15 (io), 26 ~{PSEN} (out), 27 ALE/~{PROG} (io), 28 NIC, 29 ~{EA}/VPP (in), 30 P0.7/AD7 (io), 31 P0.6/AD6 (io), 32 P0.5/AD5 (io), 33 P0.4/AD4 (io), 34 P0.3/AD3 (io), 35 P0.2/AD2 (io), 36 P0.1/AD1 (io), 37 P0.0/AD0 (io), 38 VCC (power), 39 NIC, 40 P1.0/T2 (io), 41 P1.1/T2EX (io), 42 P1.2/ECI (io), 43 P1.3/CEX0 (io), 44 P1.4/CEX1 (io)

## P80C54SFPN
designator U?
80C51 8-Bit Microcontroller Family: 256 B RAM, 16 kB ROM, 2.7V-5.5V, Low Power, High Speed
footprint SOT129-1 (DIP, Plastic; 40 Leads; Row Spacing 15.24 mm; Pitch 2.54 mm)
pins: 1 P1.0/T2 (io), 2 P1.1/T2EX (io), 3 P1.2/ECI (io), 4 P1.3/CEX0 (io), 5 P1.4/CEX1 (io), 6 P1.5/CEX2 (io), 7 P1.6/CEX3 (io), 8 P1.7/CEX4 (io), 9 RST (in), 10 P3.0/RxD (io), 11 P3.1/TxD (io), 12 P3.2/~{INT}0 (io), 13 P3.3/~{INT}1 (io), 14 P3.4/T0 (io), 15 P3.5/T1 (io), 16 P3.6/~{WR} (io), 17 P3.7/~{RD} (io), 18 XTAL2 (out), 19 XTAL1 (in), 20 VSS (power), 21 P2.0/A8 (io), 22 P2.1/A9 (io), 23 P2.2/A10 (io), 24 P2.3/A11 (io), 25 P2.4/A12 (io), 26 P2.5/A13 (io), 27 P2.6/A14 (io), 28 P2.7/A15 (io), 29 ~{PSEN} (out), 30 ALE/~{PROG} (io), 31 ~{EA}/VPP (in), 32 P0.7/AD7 (io), 33 P0.6/AD6 (io), 34 P0.5/AD5 (io), 35 P0.4/AD4 (io), 36 P0.3/AD3 (io), 37 P0.2/AD2 (io), 38 P0.1/AD1 (io), 39 P0.0/AD0 (io), 40 VCC (power)

## P80C54UBAA
designator U?
80C51 8-Bit Microcontroller Family: 256 B RAM, 16 kB ROM, 5V, Low Power, High Speed
footprint SOT187-2_N (Leaded Chip Carrier, 44-Leads, Body 16.6x16.6mm, Pitch 1.27mm, IPC Medium Density)
footprint SOT187-2_L (Leaded Chip Carrier, 44-Leads, Body 16.6x16.6mm, Pitch 1.27mm, IPC High Density)
footprint SOT187-2_M (Leaded Chip Carrier, 44-Leads, Body 16.6x16.6mm, Pitch 1.27mm, IPC Low Density)
pins: 1 NIC, 2 P1.0/T2 (io), 3 P1.1/T2EX (io), 4 P1.2/ECI (io), 5 P1.3/CEX0 (io), 6 P1.4/CEX1 (io), 7 P1.5/CEX2 (io), 8 P1.6/CEX3 (io), 9 P1.7/CEX4 (io), 10 RST (in), 11 P3.0/RxD (io), 12 NIC, 13 P3.1/TxD (io), 14 P3.2/~{INT}0 (io), 15 P3.3/~{INT}1 (io), 16 P3.4/T0 (io), 17 P3.5/T1 (io), 18 P3.6/~{WR} (io), 19 P3.7/~{RD} (io), 20 XTAL2 (out), 21 XTAL1 (in), 22 VSS (power), 23 NIC, 24 P2.0/A8 (io), 25 P2.1/A9 (io), 26 P2.2/A10 (io), 27 P2.3/A11 (io), 28 P2.4/A12 (io), 29 P2.5/A13 (io), 30 P2.6/A14 (io), 31 P2.7/A15 (io), 32 ~{PSEN} (out), 33 ALE/~{PROG} (io), 34 NIC, 35 ~{EA}/VPP (in), 36 P0.7/AD7 (io), 37 P0.6/AD6 (io), 38 P0.5/AD5 (io), 39 P0.4/AD4 (io), 40 P0.3/AD3 (io), 41 P0.2/AD2 (io), 42 P0.1/AD1 (io), 43 P0.0/AD0 (io), 44 VCC (power)

## P80C54UBBB
designator U?
80C51 8-Bit Microcontroller Family: 256 B RAM, 16 kB ROM, 5V, Low Power, High Speed
footprint SOT307-2_N (QFP, 44-Leads, Body 10x10mm, Pitch 0.8mm, IPC Medium Density)
footprint SOT307-2_L (QFP, 44-Leads, Body 10x10mm, Pitch 0.8mm, IPC High Density)
footprint SOT307-2_M (QFP, 44-Leads, Body 10x10mm, Pitch 0.8mm, IPC Low Density)
pins: 1 P1.5/CEX2 (io), 2 P1.6/CEX3 (io), 3 P1.7/CEX4 (io), 4 RST (in), 5 P3.0/RxD (io), 6 NIC, 7 P3.1/TxD (io), 8 P3.2/~{INT}0 (io), 9 P3.3/~{INT}1 (io), 10 P3.4/T0 (io), 11 P3.5/T1 (io), 12 P3.6/~{WR} (io), 13 P3.7/~{RD} (io), 14 XTAL2 (out), 15 XTAL1 (in), 16 VSS (power), 17 NIC, 18 P2.0/A8 (io), 19 P2.1/A9 (io), 20 P2.2/A10 (io), 21 P2.3/A11 (io), 22 P2.4/A12 (io), 23 P2.5/A13 (io), 24 P2.6/A14 (io), 25 P2.7/A15 (io), 26 ~{PSEN} (out), 27 ALE/~{PROG} (io), 28 NIC, 29 ~{EA}/VPP (in), 30 P0.7/AD7 (io), 31 P0.6/AD6 (io), 32 P0.5/AD5 (io), 33 P0.4/AD4 (io), 34 P0.3/AD3 (io), 35 P0.2/AD2 (io), 36 P0.1/AD1 (io), 37 P0.0/AD0 (io), 38 VCC (power), 39 NIC, 40 P1.0/T2 (io), 41 P1.1/T2EX (io), 42 P1.2/ECI (io), 43 P1.3/CEX0 (io), 44 P1.4/CEX1 (io)

## P80C54UBPN
designator U?
80C51 8-Bit Microcontroller Family: 256 B RAM, 16 kB ROM, 5V, Low Power, High Speed
footprint SOT129-1 (DIP, Plastic; 40 Leads; Row Spacing 15.24 mm; Pitch 2.54 mm)
pins: 1 P1.0/T2 (io), 2 P1.1/T2EX (io), 3 P1.2/ECI (io), 4 P1.3/CEX0 (io), 5 P1.4/CEX1 (io), 6 P1.5/CEX2 (io), 7 P1.6/CEX3 (io), 8 P1.7/CEX4 (io), 9 RST (in), 10 P3.0/RxD (io), 11 P3.1/TxD (io), 12 P3.2/~{INT}0 (io), 13 P3.3/~{INT}1 (io), 14 P3.4/T0 (io), 15 P3.5/T1 (io), 16 P3.6/~{WR} (io), 17 P3.7/~{RD} (io), 18 XTAL2 (out), 19 XTAL1 (in), 20 VSS (power), 21 P2.0/A8 (io), 22 P2.1/A9 (io), 23 P2.2/A10 (io), 24 P2.3/A11 (io), 25 P2.4/A12 (io), 26 P2.5/A13 (io), 27 P2.6/A14 (io), 28 P2.7/A15 (io), 29 ~{PSEN} (out), 30 ALE/~{PROG} (io), 31 ~{EA}/VPP (in), 32 P0.7/AD7 (io), 33 P0.6/AD6 (io), 34 P0.5/AD5 (io), 35 P0.4/AD4 (io), 36 P0.3/AD3 (io), 37 P0.2/AD2 (io), 38 P0.1/AD1 (io), 39 P0.0/AD0 (io), 40 VCC (power)

## P80C54UFAA
designator U?
80C51 8-Bit Microcontroller Family: 256 B RAM, 16 kB ROM, 5V, Low Power, High Speed
footprint SOT187-2_N (Leaded Chip Carrier, 44-Leads, Body 16.6x16.6mm, Pitch 1.27mm, IPC Medium Density)
footprint SOT187-2_L (Leaded Chip Carrier, 44-Leads, Body 16.6x16.6mm, Pitch 1.27mm, IPC High Density)
footprint SOT187-2_M (Leaded Chip Carrier, 44-Leads, Body 16.6x16.6mm, Pitch 1.27mm, IPC Low Density)
pins: 1 NIC, 2 P1.0/T2 (io), 3 P1.1/T2EX (io), 4 P1.2/ECI (io), 5 P1.3/CEX0 (io), 6 P1.4/CEX1 (io), 7 P1.5/CEX2 (io), 8 P1.6/CEX3 (io), 9 P1.7/CEX4 (io), 10 RST (in), 11 P3.0/RxD (io), 12 NIC, 13 P3.1/TxD (io), 14 P3.2/~{INT}0 (io), 15 P3.3/~{INT}1 (io), 16 P3.4/T0 (io), 17 P3.5/T1 (io), 18 P3.6/~{WR} (io), 19 P3.7/~{RD} (io), 20 XTAL2 (out), 21 XTAL1 (in), 22 VSS (power), 23 NIC, 24 P2.0/A8 (io), 25 P2.1/A9 (io), 26 P2.2/A10 (io), 27 P2.3/A11 (io), 28 P2.4/A12 (io), 29 P2.5/A13 (io), 30 P2.6/A14 (io), 31 P2.7/A15 (io), 32 ~{PSEN} (out), 33 ALE/~{PROG} (io), 34 NIC, 35 ~{EA}/VPP (in), 36 P0.7/AD7 (io), 37 P0.6/AD6 (io), 38 P0.5/AD5 (io), 39 P0.4/AD4 (io), 40 P0.3/AD3 (io), 41 P0.2/AD2 (io), 42 P0.1/AD1 (io), 43 P0.0/AD0 (io), 44 VCC (power)

## P80C54UFBB
designator U?
80C51 8-Bit Microcontroller Family: 256 B RAM, 16 kB ROM, 5V, Low Power, High Speed
footprint SOT307-2_N (QFP, 44-Leads, Body 10x10mm, Pitch 0.8mm, IPC Medium Density)
footprint SOT307-2_L (QFP, 44-Leads, Body 10x10mm, Pitch 0.8mm, IPC High Density)
footprint SOT307-2_M (QFP, 44-Leads, Body 10x10mm, Pitch 0.8mm, IPC Low Density)
pins: 1 P1.5/CEX2 (io), 2 P1.6/CEX3 (io), 3 P1.7/CEX4 (io), 4 RST (in), 5 P3.0/RxD (io), 6 NIC, 7 P3.1/TxD (io), 8 P3.2/~{INT}0 (io), 9 P3.3/~{INT}1 (io), 10 P3.4/T0 (io), 11 P3.5/T1 (io), 12 P3.6/~{WR} (io), 13 P3.7/~{RD} (io), 14 XTAL2 (out), 15 XTAL1 (in), 16 VSS (power), 17 NIC, 18 P2.0/A8 (io), 19 P2.1/A9 (io), 20 P2.2/A10 (io), 21 P2.3/A11 (io), 22 P2.4/A12 (io), 23 P2.5/A13 (io), 24 P2.6/A14 (io), 25 P2.7/A15 (io), 26 ~{PSEN} (out), 27 ALE/~{PROG} (io), 28 NIC, 29 ~{EA}/VPP (in), 30 P0.7/AD7 (io), 31 P0.6/AD6 (io), 32 P0.5/AD5 (io), 33 P0.4/AD4 (io), 34 P0.3/AD3 (io), 35 P0.2/AD2 (io), 36 P0.1/AD1 (io), 37 P0.0/AD0 (io), 38 VCC (power), 39 NIC, 40 P1.0/T2 (io), 41 P1.1/T2EX (io), 42 P1.2/ECI (io), 43 P1.3/CEX0 (io), 44 P1.4/CEX1 (io)

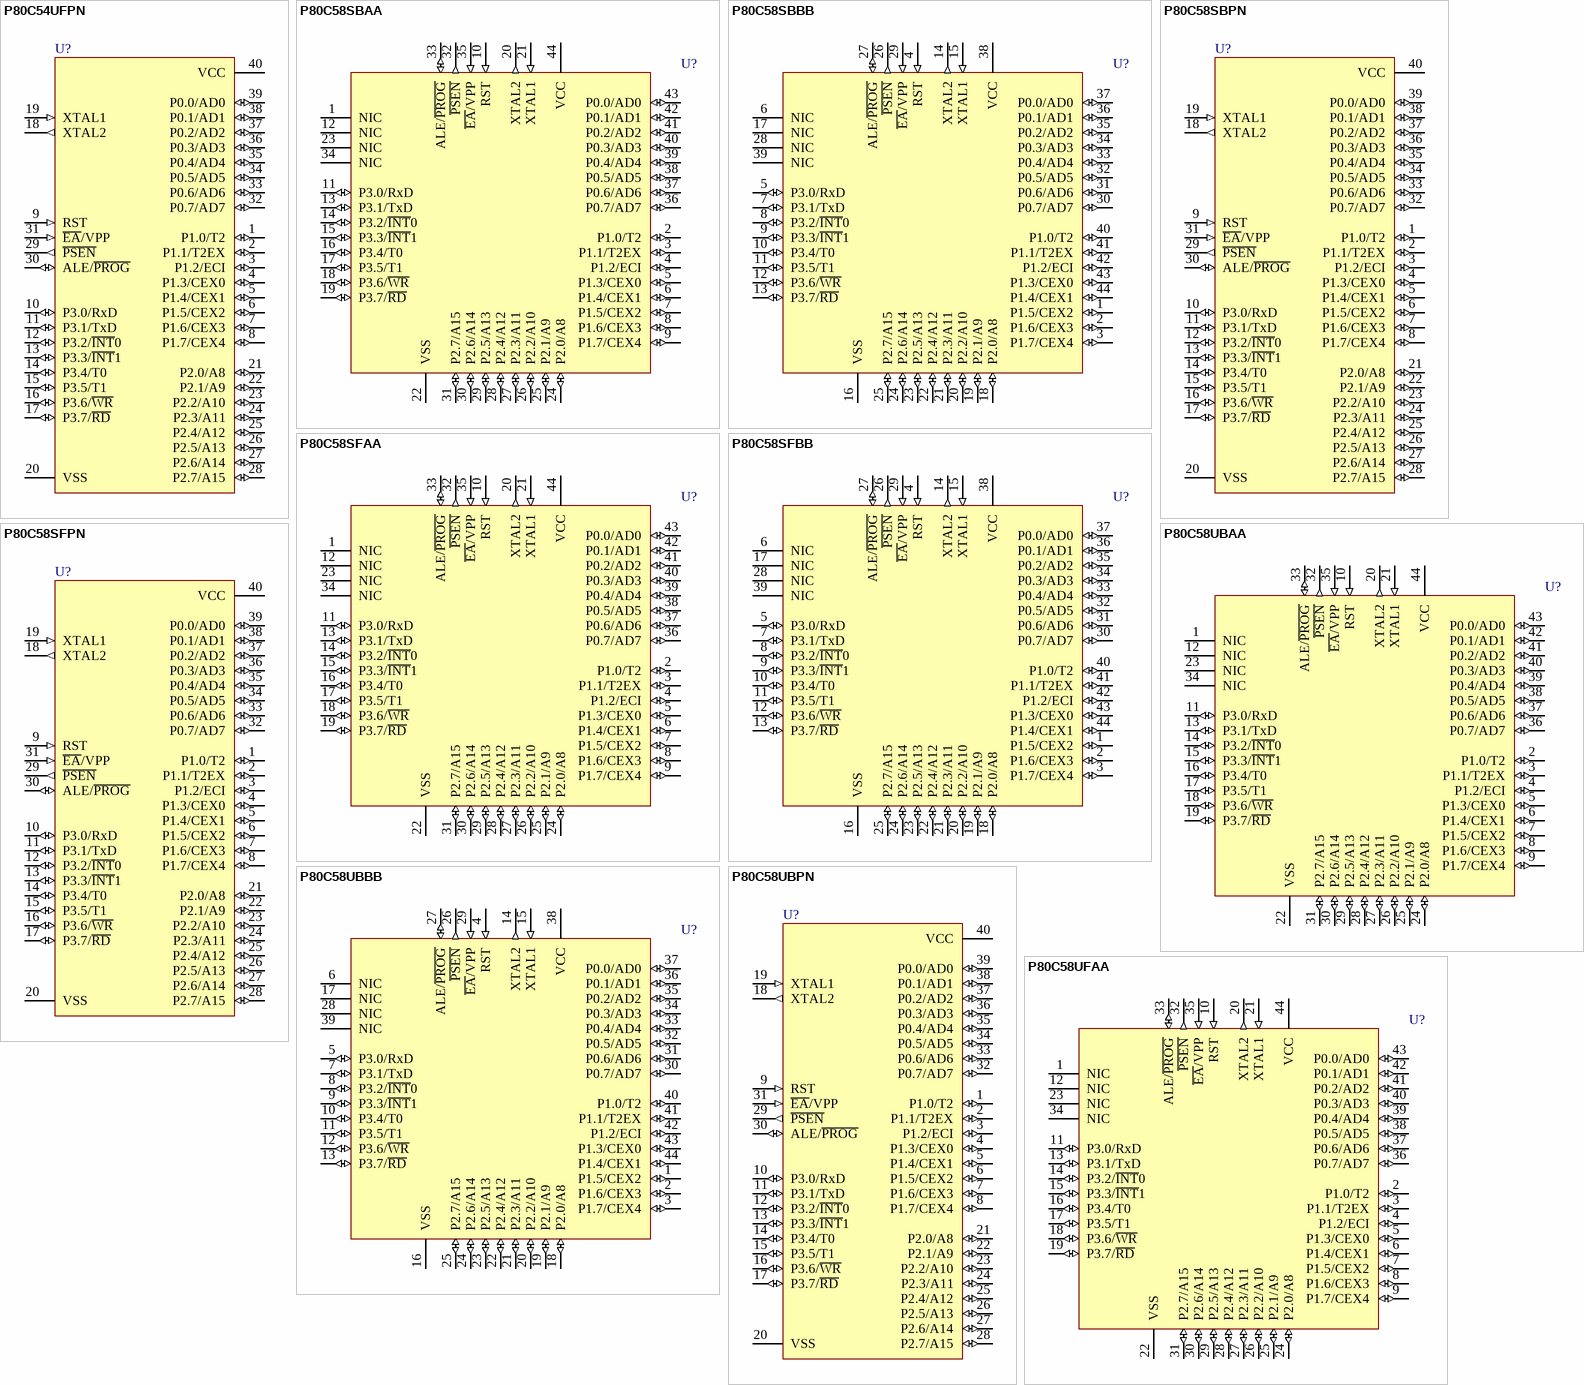
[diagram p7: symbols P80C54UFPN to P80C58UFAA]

## P80C54UFPN
designator U?
80C51 8-Bit Microcontroller Family: 256 B RAM, 16 kB ROM, 5V, Low Power, High Speed
footprint SOT129-1 (DIP, Plastic; 40 Leads; Row Spacing 15.24 mm; Pitch 2.54 mm)
pins: 1 P1.0/T2 (io), 2 P1.1/T2EX (io), 3 P1.2/ECI (io), 4 P1.3/CEX0 (io), 5 P1.4/CEX1 (io), 6 P1.5/CEX2 (io), 7 P1.6/CEX3 (io), 8 P1.7/CEX4 (io), 9 RST (in), 10 P3.0/RxD (io), 11 P3.1/TxD (io), 12 P3.2/~{INT}0 (io), 13 P3.3/~{INT}1 (io), 14 P3.4/T0 (io), 15 P3.5/T1 (io), 16 P3.6/~{WR} (io), 17 P3.7/~{RD} (io), 18 XTAL2 (out), 19 XTAL1 (in), 20 VSS (power), 21 P2.0/A8 (io), 22 P2.1/A9 (io), 23 P2.2/A10 (io), 24 P2.3/A11 (io), 25 P2.4/A12 (io), 26 P2.5/A13 (io), 27 P2.6/A14 (io), 28 P2.7/A15 (io), 29 ~{PSEN} (out), 30 ALE/~{PROG} (io), 31 ~{EA}/VPP (in), 32 P0.7/AD7 (io), 33 P0.6/AD6 (io), 34 P0.5/AD5 (io), 35 P0.4/AD4 (io), 36 P0.3/AD3 (io), 37 P0.2/AD2 (io), 38 P0.1/AD1 (io), 39 P0.0/AD0 (io), 40 VCC (power)

## P80C58SBAA
designator U?
80C51 8-Bit Microcontroller Family: 256 B RAM, 32 kB ROM, 2.7V-5.5V, Low Power, High Speed
footprint SOT187-2_N (Leaded Chip Carrier, 44-Leads, Body 16.6x16.6mm, Pitch 1.27mm, IPC Medium Density)
footprint SOT187-2_L (Leaded Chip Carrier, 44-Leads, Body 16.6x16.6mm, Pitch 1.27mm, IPC High Density)
footprint SOT187-2_M (Leaded Chip Carrier, 44-Leads, Body 16.6x16.6mm, Pitch 1.27mm, IPC Low Density)
pins: 1 NIC, 2 P1.0/T2 (io), 3 P1.1/T2EX (io), 4 P1.2/ECI (io), 5 P1.3/CEX0 (io), 6 P1.4/CEX1 (io), 7 P1.5/CEX2 (io), 8 P1.6/CEX3 (io), 9 P1.7/CEX4 (io), 10 RST (in), 11 P3.0/RxD (io), 12 NIC, 13 P3.1/TxD (io), 14 P3.2/~{INT}0 (io), 15 P3.3/~{INT}1 (io), 16 P3.4/T0 (io), 17 P3.5/T1 (io), 18 P3.6/~{WR} (io), 19 P3.7/~{RD} (io), 20 XTAL2 (out), 21 XTAL1 (in), 22 VSS (power), 23 NIC, 24 P2.0/A8 (io), 25 P2.1/A9 (io), 26 P2.2/A10 (io), 27 P2.3/A11 (io), 28 P2.4/A12 (io), 29 P2.5/A13 (io), 30 P2.6/A14 (io), 31 P2.7/A15 (io), 32 ~{PSEN} (out), 33 ALE/~{PROG} (io), 34 NIC, 35 ~{EA}/VPP (in), 36 P0.7/AD7 (io), 37 P0.6/AD6 (io), 38 P0.5/AD5 (io), 39 P0.4/AD4 (io), 40 P0.3/AD3 (io), 41 P0.2/AD2 (io), 42 P0.1/AD1 (io), 43 P0.0/AD0 (io), 44 VCC (power)

## P80C58SBBB
designator U?
80C51 8-Bit Microcontroller Family: 256 B RAM, 32 kB ROM, 2.7V-5.5V, Low Power, High Speed
footprint SOT307-2_N (QFP, 44-Leads, Body 10x10mm, Pitch 0.8mm, IPC Medium Density)
footprint SOT307-2_L (QFP, 44-Leads, Body 10x10mm, Pitch 0.8mm, IPC High Density)
footprint SOT307-2_M (QFP, 44-Leads, Body 10x10mm, Pitch 0.8mm, IPC Low Density)
pins: 1 P1.5/CEX2 (io), 2 P1.6/CEX3 (io), 3 P1.7/CEX4 (io), 4 RST (in), 5 P3.0/RxD (io), 6 NIC, 7 P3.1/TxD (io), 8 P3.2/~{INT}0 (io), 9 P3.3/~{INT}1 (io), 10 P3.4/T0 (io), 11 P3.5/T1 (io), 12 P3.6/~{WR} (io), 13 P3.7/~{RD} (io), 14 XTAL2 (out), 15 XTAL1 (in), 16 VSS (power), 17 NIC, 18 P2.0/A8 (io), 19 P2.1/A9 (io), 20 P2.2/A10 (io), 21 P2.3/A11 (io), 22 P2.4/A12 (io), 23 P2.5/A13 (io), 24 P2.6/A14 (io), 25 P2.7/A15 (io), 26 ~{PSEN} (out), 27 ALE/~{PROG} (io), 28 NIC, 29 ~{EA}/VPP (in), 30 P0.7/AD7 (io), 31 P0.6/AD6 (io), 32 P0.5/AD5 (io), 33 P0.4/AD4 (io), 34 P0.3/AD3 (io), 35 P0.2/AD2 (io), 36 P0.1/AD1 (io), 37 P0.0/AD0 (io), 38 VCC (power), 39 NIC, 40 P1.0/T2 (io), 41 P1.1/T2EX (io), 42 P1.2/ECI (io), 43 P1.3/CEX0 (io), 44 P1.4/CEX1 (io)

## P80C58SBPN
designator U?
80C51 8-Bit Microcontroller Family: 256 B RAM, 32 kB ROM, 2.7V-5.5V, Low Power, High Speed
footprint SOT129-1 (DIP, Plastic; 40 Leads; Row Spacing 15.24 mm; Pitch 2.54 mm)
pins: 1 P1.0/T2 (io), 2 P1.1/T2EX (io), 3 P1.2/ECI (io), 4 P1.3/CEX0 (io), 5 P1.4/CEX1 (io), 6 P1.5/CEX2 (io), 7 P1.6/CEX3 (io), 8 P1.7/CEX4 (io), 9 RST (in), 10 P3.0/RxD (io), 11 P3.1/TxD (io), 12 P3.2/~{INT}0 (io), 13 P3.3/~{INT}1 (io), 14 P3.4/T0 (io), 15 P3.5/T1 (io), 16 P3.6/~{WR} (io), 17 P3.7/~{RD} (io), 18 XTAL2 (out), 19 XTAL1 (in), 20 VSS (power), 21 P2.0/A8 (io), 22 P2.1/A9 (io), 23 P2.2/A10 (io), 24 P2.3/A11 (io), 25 P2.4/A12 (io), 26 P2.5/A13 (io), 27 P2.6/A14 (io), 28 P2.7/A15 (io), 29 ~{PSEN} (out), 30 ALE/~{PROG} (io), 31 ~{EA}/VPP (in), 32 P0.7/AD7 (io), 33 P0.6/AD6 (io), 34 P0.5/AD5 (io), 35 P0.4/AD4 (io), 36 P0.3/AD3 (io), 37 P0.2/AD2 (io), 38 P0.1/AD1 (io), 39 P0.0/AD0 (io), 40 VCC (power)

## P80C58SFAA
designator U?
80C51 8-Bit Microcontroller Family: 256 B RAM, 32 kB ROM, 2.7V-5.5V, Low Power, High Speed
footprint SOT187-2_N (Leaded Chip Carrier, 44-Leads, Body 16.6x16.6mm, Pitch 1.27mm, IPC Medium Density)
footprint SOT187-2_L (Leaded Chip Carrier, 44-Leads, Body 16.6x16.6mm, Pitch 1.27mm, IPC High Density)
footprint SOT187-2_M (Leaded Chip Carrier, 44-Leads, Body 16.6x16.6mm, Pitch 1.27mm, IPC Low Density)
pins: 1 NIC, 2 P1.0/T2 (io), 3 P1.1/T2EX (io), 4 P1.2/ECI (io), 5 P1.3/CEX0 (io), 6 P1.4/CEX1 (io), 7 P1.5/CEX2 (io), 8 P1.6/CEX3 (io), 9 P1.7/CEX4 (io), 10 RST (in), 11 P3.0/RxD (io), 12 NIC, 13 P3.1/TxD (io), 14 P3.2/~{INT}0 (io), 15 P3.3/~{INT}1 (io), 16 P3.4/T0 (io), 17 P3.5/T1 (io), 18 P3.6/~{WR} (io), 19 P3.7/~{RD} (io), 20 XTAL2 (out), 21 XTAL1 (in), 22 VSS (power), 23 NIC, 24 P2.0/A8 (io), 25 P2.1/A9 (io), 26 P2.2/A10 (io), 27 P2.3/A11 (io), 28 P2.4/A12 (io), 29 P2.5/A13 (io), 30 P2.6/A14 (io), 31 P2.7/A15 (io), 32 ~{PSEN} (out), 33 ALE/~{PROG} (io), 34 NIC, 35 ~{EA}/VPP (in), 36 P0.7/AD7 (io), 37 P0.6/AD6 (io), 38 P0.5/AD5 (io), 39 P0.4/AD4 (io), 40 P0.3/AD3 (io), 41 P0.2/AD2 (io), 42 P0.1/AD1 (io), 43 P0.0/AD0 (io), 44 VCC (power)

## P80C58SFBB
designator U?
80C51 8-Bit Microcontroller Family: 256 B RAM, 32 kB ROM, 2.7V-5.5V, Low Power, High Speed
footprint SOT307-2_N (QFP, 44-Leads, Body 10x10mm, Pitch 0.8mm, IPC Medium Density)
footprint SOT307-2_L (QFP, 44-Leads, Body 10x10mm, Pitch 0.8mm, IPC High Density)
footprint SOT307-2_M (QFP, 44-Leads, Body 10x10mm, Pitch 0.8mm, IPC Low Density)
pins: 1 P1.5/CEX2 (io), 2 P1.6/CEX3 (io), 3 P1.7/CEX4 (io), 4 RST (in), 5 P3.0/RxD (io), 6 NIC, 7 P3.1/TxD (io), 8 P3.2/~{INT}0 (io), 9 P3.3/~{INT}1 (io), 10 P3.4/T0 (io), 11 P3.5/T1 (io), 12 P3.6/~{WR} (io), 13 P3.7/~{RD} (io), 14 XTAL2 (out), 15 XTAL1 (in), 16 VSS (power), 17 NIC, 18 P2.0/A8 (io), 19 P2.1/A9 (io), 20 P2.2/A10 (io), 21 P2.3/A11 (io), 22 P2.4/A12 (io), 23 P2.5/A13 (io), 24 P2.6/A14 (io), 25 P2.7/A15 (io), 26 ~{PSEN} (out), 27 ALE/~{PROG} (io), 28 NIC, 29 ~{EA}/VPP (in), 30 P0.7/AD7 (io), 31 P0.6/AD6 (io), 32 P0.5/AD5 (io), 33 P0.4/AD4 (io), 34 P0.3/AD3 (io), 35 P0.2/AD2 (io), 36 P0.1/AD1 (io), 37 P0.0/AD0 (io), 38 VCC (power), 39 NIC, 40 P1.0/T2 (io), 41 P1.1/T2EX (io), 42 P1.2/ECI (io), 43 P1.3/CEX0 (io), 44 P1.4/CEX1 (io)

## P80C58SFPN
designator U?
80C51 8-Bit Microcontroller Family: 256 B RAM, 32 kB ROM, 2.7V-5.5V, Low Power, High Speed
footprint SOT129-1 (DIP, Plastic; 40 Leads; Row Spacing 15.24 mm; Pitch 2.54 mm)
pins: 1 P1.0/T2 (io), 2 P1.1/T2EX (io), 3 P1.2/ECI (io), 4 P1.3/CEX0 (io), 5 P1.4/CEX1 (io), 6 P1.5/CEX2 (io), 7 P1.6/CEX3 (io), 8 P1.7/CEX4 (io), 9 RST (in), 10 P3.0/RxD (io), 11 P3.1/TxD (io), 12 P3.2/~{INT}0 (io), 13 P3.3/~{INT}1 (io), 14 P3.4/T0 (io), 15 P3.5/T1 (io), 16 P3.6/~{WR} (io), 17 P3.7/~{RD} (io), 18 XTAL2 (out), 19 XTAL1 (in), 20 VSS (power), 21 P2.0/A8 (io), 22 P2.1/A9 (io), 23 P2.2/A10 (io), 24 P2.3/A11 (io), 25 P2.4/A12 (io), 26 P2.5/A13 (io), 27 P2.6/A14 (io), 28 P2.7/A15 (io), 29 ~{PSEN} (out), 30 ALE/~{PROG} (io), 31 ~{EA}/VPP (in), 32 P0.7/AD7 (io), 33 P0.6/AD6 (io), 34 P0.5/AD5 (io), 35 P0.4/AD4 (io), 36 P0.3/AD3 (io), 37 P0.2/AD2 (io), 38 P0.1/AD1 (io), 39 P0.0/AD0 (io), 40 VCC (power)

## P80C58UBAA
designator U?
80C51 8-Bit Microcontroller Family: 256 B RAM, 32 kB ROM, 5V, Low Power, High Speed
footprint SOT187-2_N (Leaded Chip Carrier, 44-Leads, Body 16.6x16.6mm, Pitch 1.27mm, IPC Medium Density)
footprint SOT187-2_L (Leaded Chip Carrier, 44-Leads, Body 16.6x16.6mm, Pitch 1.27mm, IPC High Density)
footprint SOT187-2_M (Leaded Chip Carrier, 44-Leads, Body 16.6x16.6mm, Pitch 1.27mm, IPC Low Density)
pins: 1 NIC, 2 P1.0/T2 (io), 3 P1.1/T2EX (io), 4 P1.2/ECI (io), 5 P1.3/CEX0 (io), 6 P1.4/CEX1 (io), 7 P1.5/CEX2 (io), 8 P1.6/CEX3 (io), 9 P1.7/CEX4 (io), 10 RST (in), 11 P3.0/RxD (io), 12 NIC, 13 P3.1/TxD (io), 14 P3.2/~{INT}0 (io), 15 P3.3/~{INT}1 (io), 16 P3.4/T0 (io), 17 P3.5/T1 (io), 18 P3.6/~{WR} (io), 19 P3.7/~{RD} (io), 20 XTAL2 (out), 21 XTAL1 (in), 22 VSS (power), 23 NIC, 24 P2.0/A8 (io), 25 P2.1/A9 (io), 26 P2.2/A10 (io), 27 P2.3/A11 (io), 28 P2.4/A12 (io), 29 P2.5/A13 (io), 30 P2.6/A14 (io), 31 P2.7/A15 (io), 32 ~{PSEN} (out), 33 ALE/~{PROG} (io), 34 NIC, 35 ~{EA}/VPP (in), 36 P0.7/AD7 (io), 37 P0.6/AD6 (io), 38 P0.5/AD5 (io), 39 P0.4/AD4 (io), 40 P0.3/AD3 (io), 41 P0.2/AD2 (io), 42 P0.1/AD1 (io), 43 P0.0/AD0 (io), 44 VCC (power)

## P80C58UBBB
designator U?
80C51 8-Bit Microcontroller Family: 256 B RAM, 32 kB ROM, 5V, Low Power, High Speed
footprint SOT307-2_N (QFP, 44-Leads, Body 10x10mm, Pitch 0.8mm, IPC Medium Density)
footprint SOT307-2_L (QFP, 44-Leads, Body 10x10mm, Pitch 0.8mm, IPC High Density)
footprint SOT307-2_M (QFP, 44-Leads, Body 10x10mm, Pitch 0.8mm, IPC Low Density)
pins: 1 P1.5/CEX2 (io), 2 P1.6/CEX3 (io), 3 P1.7/CEX4 (io), 4 RST (in), 5 P3.0/RxD (io), 6 NIC, 7 P3.1/TxD (io), 8 P3.2/~{INT}0 (io), 9 P3.3/~{INT}1 (io), 10 P3.4/T0 (io), 11 P3.5/T1 (io), 12 P3.6/~{WR} (io), 13 P3.7/~{RD} (io), 14 XTAL2 (out), 15 XTAL1 (in), 16 VSS (power), 17 NIC, 18 P2.0/A8 (io), 19 P2.1/A9 (io), 20 P2.2/A10 (io), 21 P2.3/A11 (io), 22 P2.4/A12 (io), 23 P2.5/A13 (io), 24 P2.6/A14 (io), 25 P2.7/A15 (io), 26 ~{PSEN} (out), 27 ALE/~{PROG} (io), 28 NIC, 29 ~{EA}/VPP (in), 30 P0.7/AD7 (io), 31 P0.6/AD6 (io), 32 P0.5/AD5 (io), 33 P0.4/AD4 (io), 34 P0.3/AD3 (io), 35 P0.2/AD2 (io), 36 P0.1/AD1 (io), 37 P0.0/AD0 (io), 38 VCC (power), 39 NIC, 40 P1.0/T2 (io), 41 P1.1/T2EX (io), 42 P1.2/ECI (io), 43 P1.3/CEX0 (io), 44 P1.4/CEX1 (io)

## P80C58UBPN
designator U?
80C51 8-Bit Microcontroller Family: 256 B RAM, 32 kB ROM, 5V, Low Power, High Speed
footprint SOT129-1 (DIP, Plastic; 40 Leads; Row Spacing 15.24 mm; Pitch 2.54 mm)
pins: 1 P1.0/T2 (io), 2 P1.1/T2EX (io), 3 P1.2/ECI (io), 4 P1.3/CEX0 (io), 5 P1.4/CEX1 (io), 6 P1.5/CEX2 (io), 7 P1.6/CEX3 (io), 8 P1.7/CEX4 (io), 9 RST (in), 10 P3.0/RxD (io), 11 P3.1/TxD (io), 12 P3.2/~{INT}0 (io), 13 P3.3/~{INT}1 (io), 14 P3.4/T0 (io), 15 P3.5/T1 (io), 16 P3.6/~{WR} (io), 17 P3.7/~{RD} (io), 18 XTAL2 (out), 19 XTAL1 (in), 20 VSS (power), 21 P2.0/A8 (io), 22 P2.1/A9 (io), 23 P2.2/A10 (io), 24 P2.3/A11 (io), 25 P2.4/A12 (io), 26 P2.5/A13 (io), 27 P2.6/A14 (io), 28 P2.7/A15 (io), 29 ~{PSEN} (out), 30 ALE/~{PROG} (io), 31 ~{EA}/VPP (in), 32 P0.7/AD7 (io), 33 P0.6/AD6 (io), 34 P0.5/AD5 (io), 35 P0.4/AD4 (io), 36 P0.3/AD3 (io), 37 P0.2/AD2 (io), 38 P0.1/AD1 (io), 39 P0.0/AD0 (io), 40 VCC (power)

## P80C58UFAA
designator U?
80C51 8-Bit Microcontroller Family: 256 B RAM, 32 kB ROM, 5V, Low Power, High Speed
footprint SOT187-2_N (Leaded Chip Carrier, 44-Leads, Body 16.6x16.6mm, Pitch 1.27mm, IPC Medium Density)
footprint SOT187-2_L (Leaded Chip Carrier, 44-Leads, Body 16.6x16.6mm, Pitch 1.27mm, IPC High Density)
footprint SOT187-2_M (Leaded Chip Carrier, 44-Leads, Body 16.6x16.6mm, Pitch 1.27mm, IPC Low Density)
pins: 1 NIC, 2 P1.0/T2 (io), 3 P1.1/T2EX (io), 4 P1.2/ECI (io), 5 P1.3/CEX0 (io), 6 P1.4/CEX1 (io), 7 P1.5/CEX2 (io), 8 P1.6/CEX3 (io), 9 P1.7/CEX4 (io), 10 RST (in), 11 P3.0/RxD (io), 12 NIC, 13 P3.1/TxD (io), 14 P3.2/~{INT}0 (io), 15 P3.3/~{INT}1 (io), 16 P3.4/T0 (io), 17 P3.5/T1 (io), 18 P3.6/~{WR} (io), 19 P3.7/~{RD} (io), 20 XTAL2 (out), 21 XTAL1 (in), 22 VSS (power), 23 NIC, 24 P2.0/A8 (io), 25 P2.1/A9 (io), 26 P2.2/A10 (io), 27 P2.3/A11 (io), 28 P2.4/A12 (io), 29 P2.5/A13 (io), 30 P2.6/A14 (io), 31 P2.7/A15 (io), 32 ~{PSEN} (out), 33 ALE/~{PROG} (io), 34 NIC, 35 ~{EA}/VPP (in), 36 P0.7/AD7 (io), 37 P0.6/AD6 (io), 38 P0.5/AD5 (io), 39 P0.4/AD4 (io), 40 P0.3/AD3 (io), 41 P0.2/AD2 (io), 42 P0.1/AD1 (io), 43 P0.0/AD0 (io), 44 VCC (power)

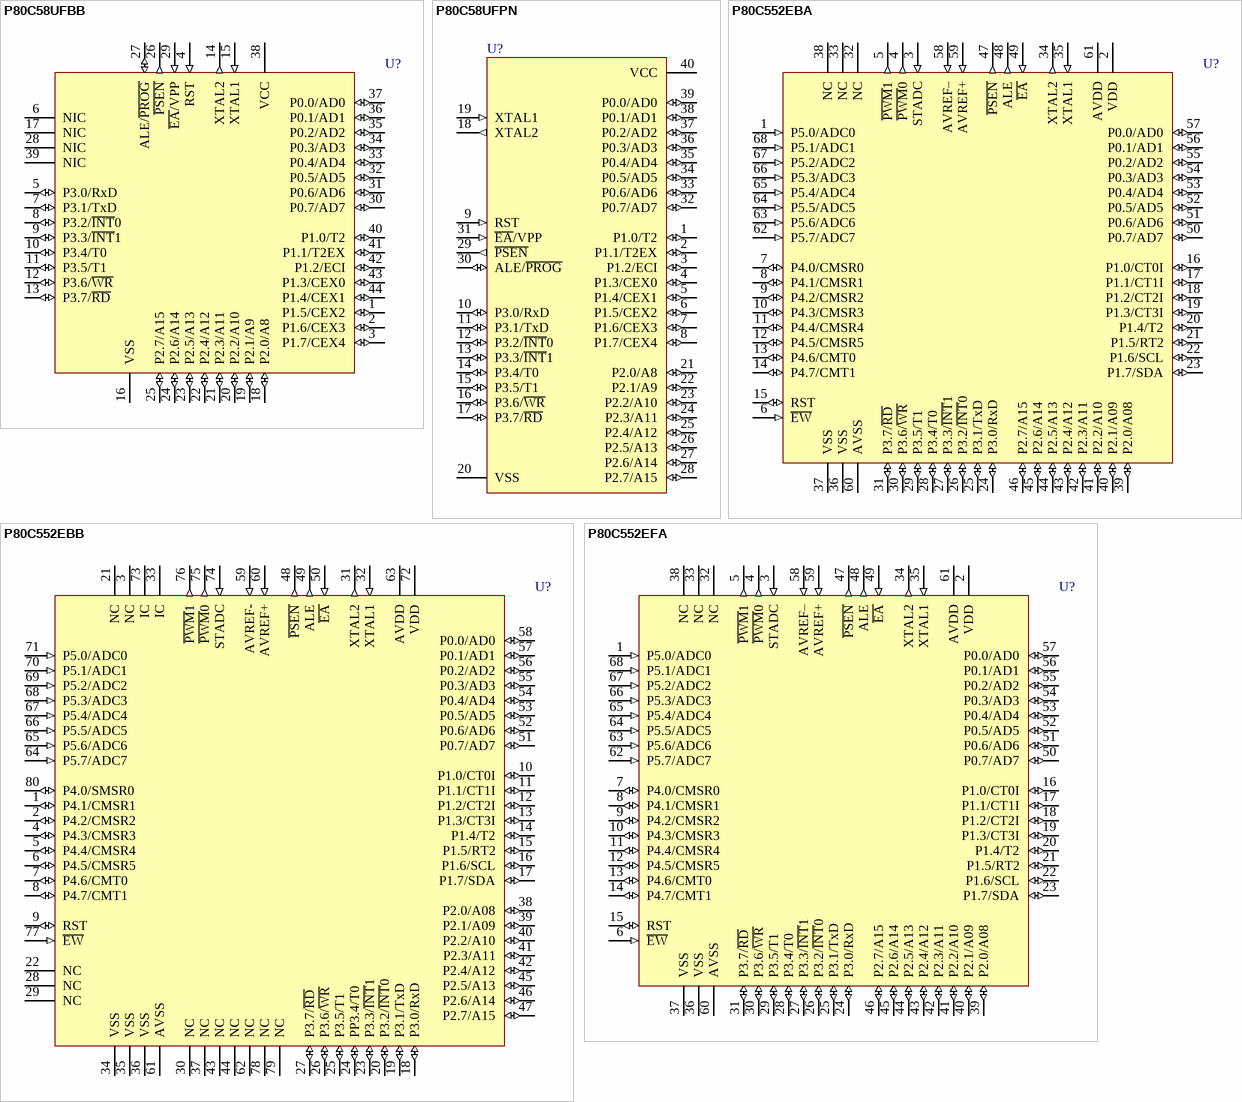
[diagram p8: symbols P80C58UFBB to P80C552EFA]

## P80C58UFBB
designator U?
80C51 8-Bit Microcontroller Family: 256 B RAM, 32 kB ROM, 5V, Low Power, High Speed
footprint SOT307-2_N (QFP, 44-Leads, Body 10x10mm, Pitch 0.8mm, IPC Medium Density)
footprint SOT307-2_L (QFP, 44-Leads, Body 10x10mm, Pitch 0.8mm, IPC High Density)
footprint SOT307-2_M (QFP, 44-Leads, Body 10x10mm, Pitch 0.8mm, IPC Low Density)
pins: 1 P1.5/CEX2 (io), 2 P1.6/CEX3 (io), 3 P1.7/CEX4 (io), 4 RST (in), 5 P3.0/RxD (io), 6 NIC, 7 P3.1/TxD (io), 8 P3.2/~{INT}0 (io), 9 P3.3/~{INT}1 (io), 10 P3.4/T0 (io), 11 P3.5/T1 (io), 12 P3.6/~{WR} (io), 13 P3.7/~{RD} (io), 14 XTAL2 (out), 15 XTAL1 (in), 16 VSS (power), 17 NIC, 18 P2.0/A8 (io), 19 P2.1/A9 (io), 20 P2.2/A10 (io), 21 P2.3/A11 (io), 22 P2.4/A12 (io), 23 P2.5/A13 (io), 24 P2.6/A14 (io), 25 P2.7/A15 (io), 26 ~{PSEN} (out), 27 ALE/~{PROG} (io), 28 NIC, 29 ~{EA}/VPP (in), 30 P0.7/AD7 (io), 31 P0.6/AD6 (io), 32 P0.5/AD5 (io), 33 P0.4/AD4 (io), 34 P0.3/AD3 (io), 35 P0.2/AD2 (io), 36 P0.1/AD1 (io), 37 P0.0/AD0 (io), 38 VCC (power), 39 NIC, 40 P1.0/T2 (io), 41 P1.1/T2EX (io), 42 P1.2/ECI (io), 43 P1.3/CEX0 (io), 44 P1.4/CEX1 (io)

## P80C58UFPN
designator U?
80C51 8-Bit Microcontroller Family: 256 B RAM, 32 kB ROM, 5V, Low Power, High Speed
footprint SOT129-1 (DIP, Plastic; 40 Leads; Row Spacing 15.24 mm; Pitch 2.54 mm)
pins: 1 P1.0/T2 (io), 2 P1.1/T2EX (io), 3 P1.2/ECI (io), 4 P1.3/CEX0 (io), 5 P1.4/CEX1 (io), 6 P1.5/CEX2 (io), 7 P1.6/CEX3 (io), 8 P1.7/CEX4 (io), 9 RST (in), 10 P3.0/RxD (io), 11 P3.1/TxD (io), 12 P3.2/~{INT}0 (io), 13 P3.3/~{INT}1 (io), 14 P3.4/T0 (io), 15 P3.5/T1 (io), 16 P3.6/~{WR} (io), 17 P3.7/~{RD} (io), 18 XTAL2 (out), 19 XTAL1 (in), 20 VSS (power), 21 P2.0/A8 (io), 22 P2.1/A9 (io), 23 P2.2/A10 (io), 24 P2.3/A11 (io), 25 P2.4/A12 (io), 26 P2.5/A13 (io), 27 P2.6/A14 (io), 28 P2.7/A15 (io), 29 ~{PSEN} (out), 30 ALE/~{PROG} (io), 31 ~{EA}/VPP (in), 32 P0.7/AD7 (io), 33 P0.6/AD6 (io), 34 P0.5/AD5 (io), 35 P0.4/AD4 (io), 36 P0.3/AD3 (io), 37 P0.2/AD2 (io), 38 P0.1/AD1 (io), 39 P0.0/AD0 (io), 40 VCC (power)

## P80C552EBA
designator U?
ROMless, Single-Chip 8-Bit Microcontroller with 10-bit A/D, Capture/Compare Timer, High-Speed Outputs, PWM
footprint SOT188-2_N (Leaded Chip Carrier, 68-Leads, Body 24.2x24.2mm, Pitch 1.27mm, IPC Medium Density)
footprint SOT188-2_L (Leaded Chip Carrier, 68-Leads, Body 24.2x24.2mm, Pitch 1.27mm, IPC High Density)
footprint SOT188-2_M (Leaded Chip Carrier, 68-Leads, Body 24.2x24.2mm, Pitch 1.27mm, IPC Low Density)
pins: 1 P5.0/ADC0 (in), 2 VDD (power), 3 STADC (in), 4 ~{PWM}0 (out), 5 ~{PWM}1 (out), 6 ~{EW} (in), 7 P4.0/CMSR0 (io), 8 P4.1/CMSR1 (io), 9 P4.2/CMSR2 (io), 10 P4.3/CMSR3 (io), 11 P4.4/CMSR4 (io), 12 P4.5/CMSR5 (io), 13 P4.6/CMT0 (io), 14 P4.7/CMT1 (io), 15 RST (io), 16 P1.0/CT0I (io), 17 P1.1/CT1I (io), 18 P1.2/CT2I (io), 19 P1.3/CT3I (io), 20 P1.4/T2 (io), 21 P1.5/RT2 (io), 22 P1.6/SCL (io), 23 P1.7/SDA (io), 24 P3.0/RxD (io), 25 P3.1/TxD (io), 26 P3.2/~{INT}0 (io), 27 P3.3/~{INT}1 (io), 28 P3.4/T0 (io), 29 P3.5/T1 (io), 30 P3.6/~{WR} (io), 31 P3.7/~{RD} (io), 32 NC, 33 NC, 34 XTAL2 (out), 35 XTAL1 (in), 36 VSS (power), 37 VSS (power), 38 NC, 39 P2.0/A08 (io), 40 P2.1/A09 (io), 41 P2.2/A10 (io), 42 P2.3/A11 (io), 43 P2.4/A12 (io), 44 P2.5/A13 (io), 45 P2.6/A14 (io), 46 P2.7/A15 (io), 47 ~{PSEN} (out), 48 ALE (out), 49 ~{EA} (in), 50 P0.7/AD7 (io), 51 P0.6/AD6 (io), 52 P0.5/AD5 (io), 53 P0.4/AD4 (io), 54 P0.3/AD3 (io), 55 P0.2/AD2 (io), 56 P0.1/AD1 (io), 57 P0.0/AD0 (io), 58 AVREF– (in), 59 AVREF+ (in), 60 AVSS (power), 61 AVDD (power), 62 P5.7/ADC7 (in), 63 P5.6/ADC6 (in), 64 P5.5/ADC5 (in), 65 P5.4/ADC4 (in), 66 P5.3/ADC3 (in), 67 P5.2/ADC2 (in), 68 P5.1/ADC1 (in)

## P80C552EBB
designator U?
ROMless, Single-Chip 8-Bit Microcontroller with 10-bit A/D, Capture/Compare Timer, High-Speed Outputs, PWM; DoNotConnect: Pins 33 & 73 are internally connected (IC), do not use.
footprint SOT318-2_N (QFP, 80-Leads, Body 20x14mm, Pitch 0.8mm, IPC Medium Density)
footprint SOT318-2_L (QFP, 80-Leads, Body 20x14mm, Pitch 0.8mm, IPC High Density)
footprint SOT318-2_M (QFP, 80-Leads, Body 20x14mm, Pitch 0.8mm, IPC Low Density)
pins: 1 P4.1/CMSR1 (io), 2 P4.2/CMSR2 (io), 3 NC, 4 P4.3/CMSR3 (io), 5 P4.4/CMSR4 (io), 6 P4.5/CMSR5 (io), 7 P4.6/CMT0 (io), 8 P4.7/CMT1 (io), 9 RST (io), 10 P1.0/CT0I (io), 11 P1.1/CT1I (io), 12 P1.2/CT2I (io), 13 P1.3/CT3I (io), 14 P1.4/T2 (io), 15 P1.5/RT2 (io), 16 P1.6/SCL (io), 17 P1.7/SDA (io), 18 P3.0/RxD (io), 19 P3.1/TxD (io), 20 P3.2/~{INT}0 (io), 21 NC, 22 NC, 23 P3.3/~{INT}1 (io), 24 PP3.4/T0 (io), 25 P3.5/T1 (io), 26 P3.6/~{WR} (io), 27 P3.7/~{RD} (io), 28 NC, 29 NC, 30 NC, 31 XTAL2 (out), 32 XTAL1 (in), 33 IC, 34 VSS (power), 35 VSS (power), 36 VSS (power), 37 NC, 38 P2.0/A08 (io), 39 P2.1/A09 (io), 40 P2.2/A10 (io), 41 P2.3/A11 (io), 42 P2.4/A12 (io), 43 NC, 44 NC, 45 P2.5/A13 (io), 46 P2.6/A14 (io), 47 P2.7/A15 (io), 48 ~{PSEN} (out), 49 ALE (out), 50 ~{EA} (in), 51 P0.7/AD7 (io), 52 P0.6/AD6 (io), 53 P0.5/AD5 (io), 54 P0.4/AD4 (io), 55 P0.3/AD3 (io), 56 P0.2/AD2 (io), 57 P0.1/AD1 (io), 58 P0.0/AD0 (io), 59 AVREF- (in), 60 AVREF+ (in), 61 AVSS (power), 62 NC, 63 AVDD (power), 64 P5.7/ADC7 (in), 65 P5.6/ADC6 (in), 66 P5.5/ADC5 (in), 67 P5.4/ADC4 (in), 68 P5.3/ADC3 (in), 69 P5.2/ADC2 (in), 70 P5.1/ADC1 (in), 71 P5.0/ADC0 (in), 72 VDD (power), 73 IC, 74 STADC (in), 75 ~{PWM}0 (out), 76 ~{PWM}1 (out), 77 ~{EW} (in), 78 NC, 79 NC, 80 P4.0/SMSR0 (io)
